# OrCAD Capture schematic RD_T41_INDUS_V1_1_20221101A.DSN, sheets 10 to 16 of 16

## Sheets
10 PAGE04_POWER-SUPPLY: size A3; note: POWER-SUPPLY
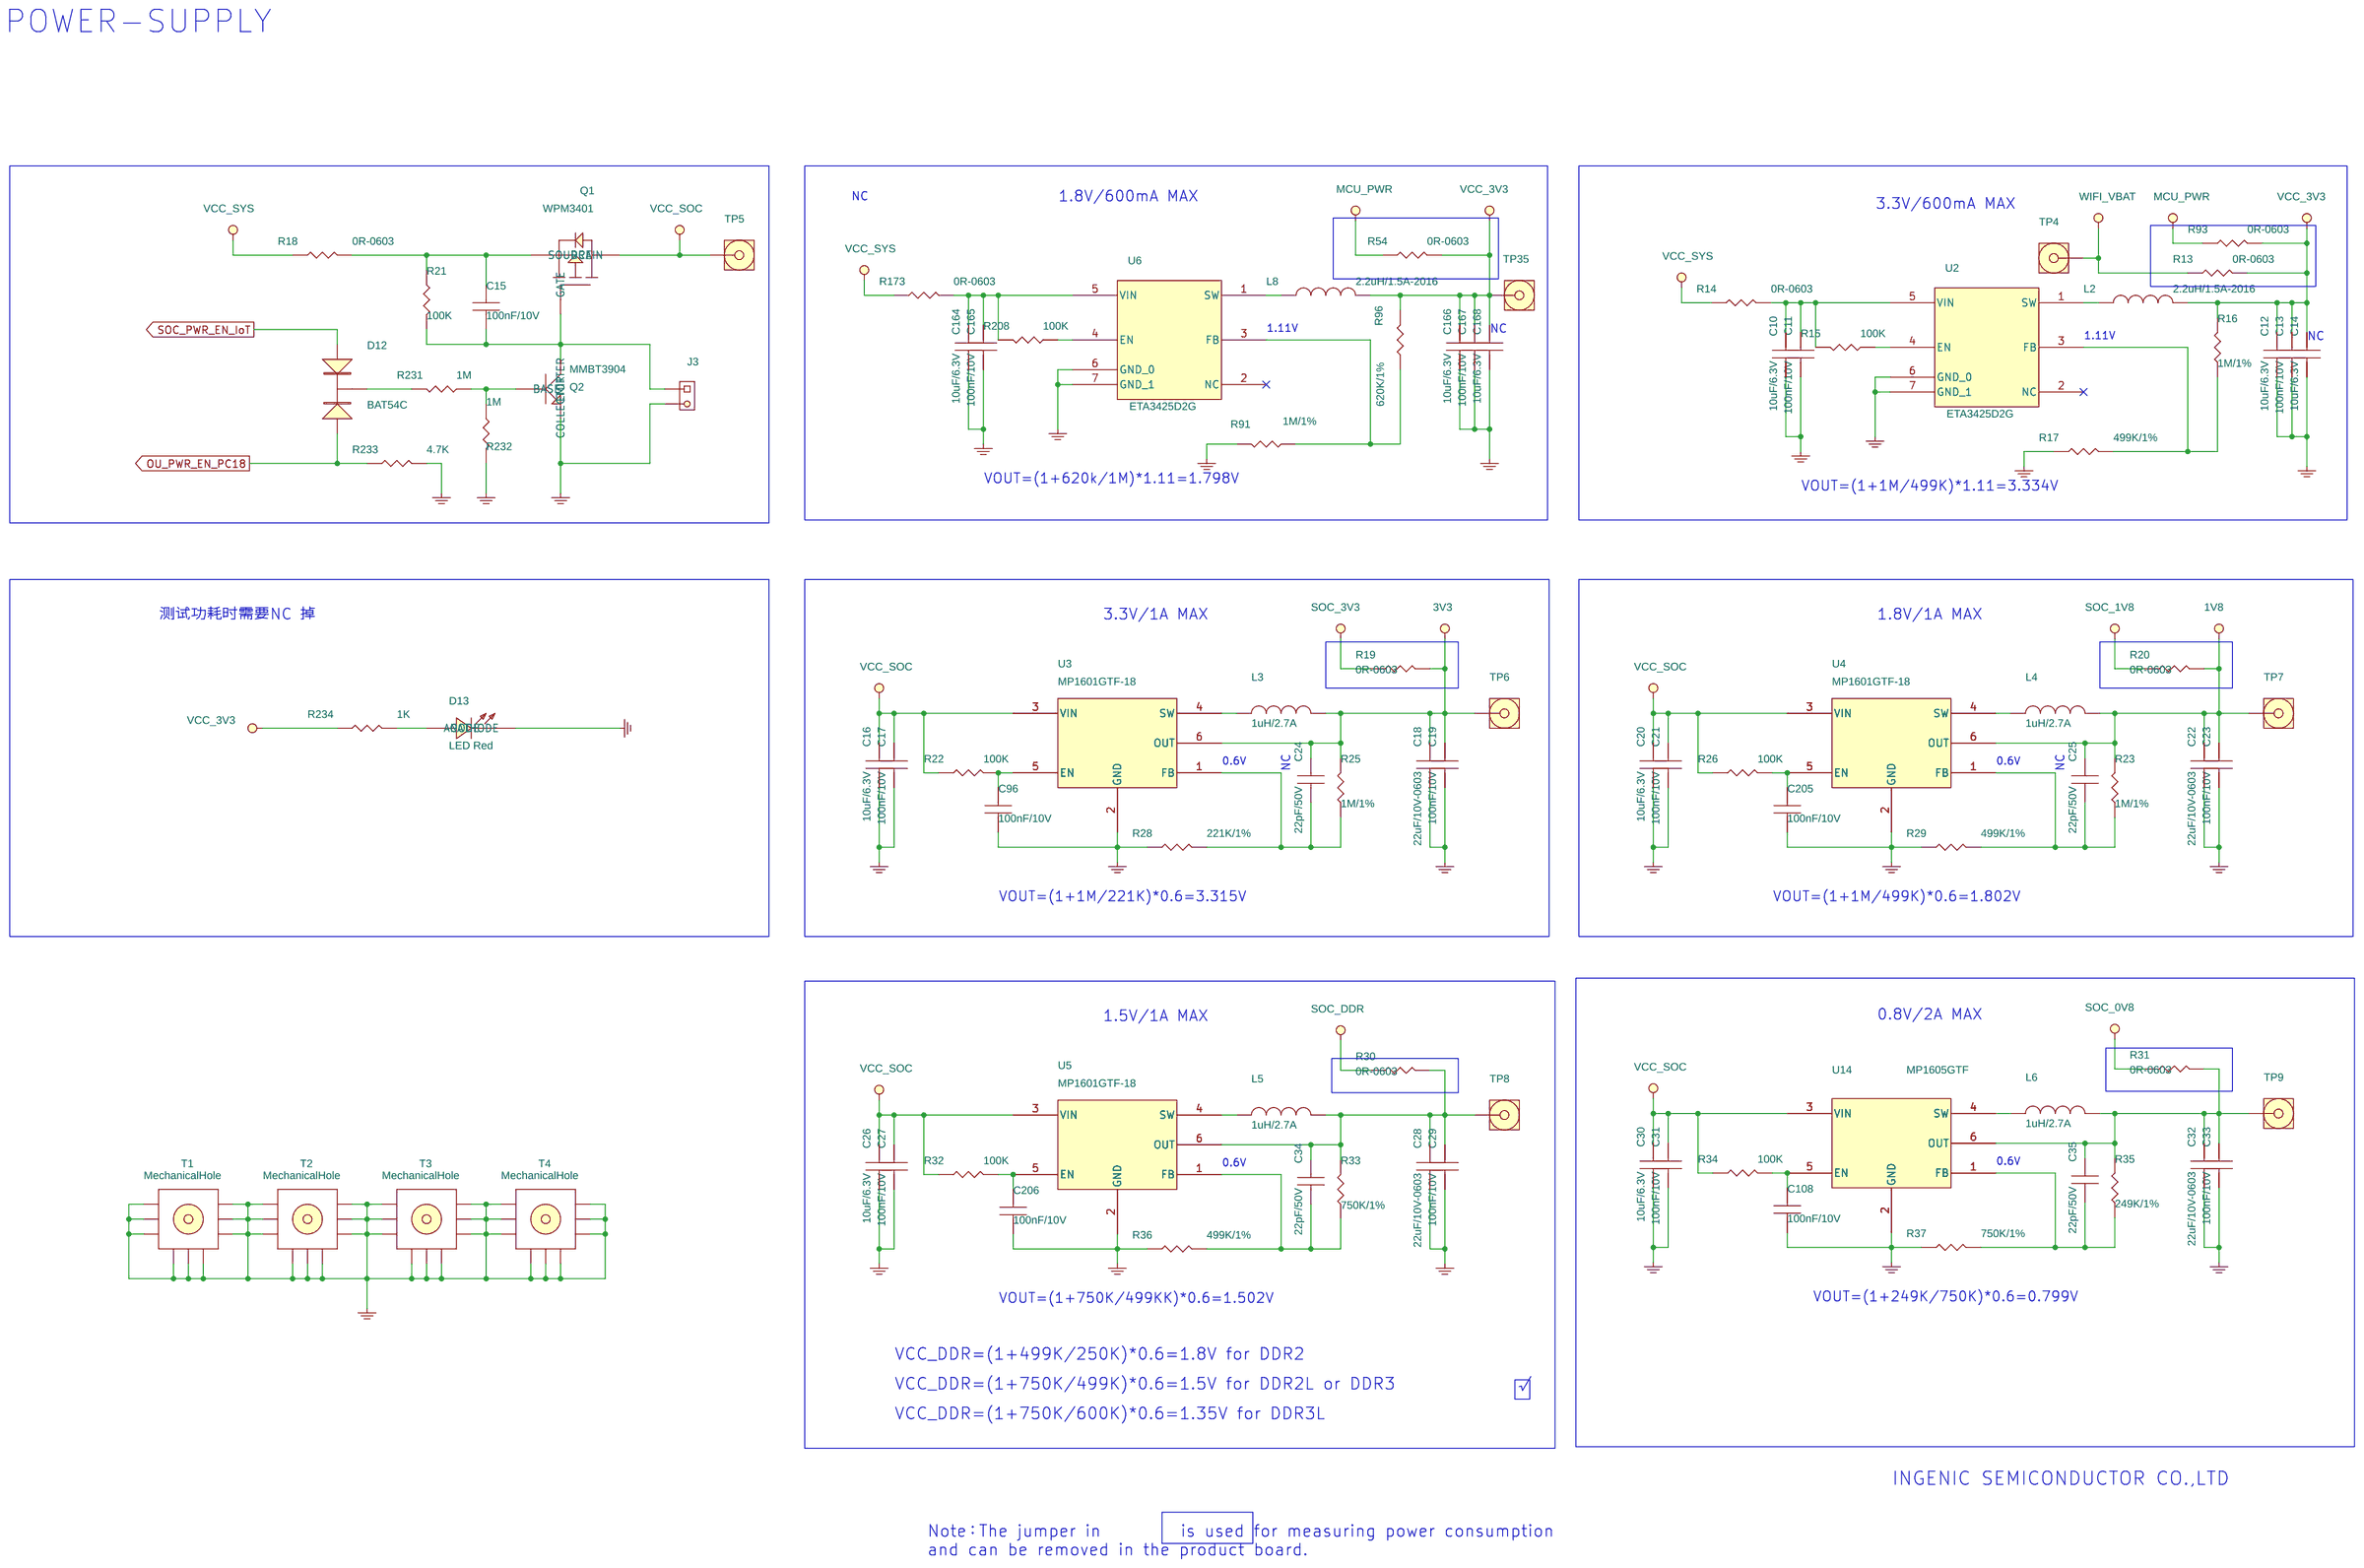
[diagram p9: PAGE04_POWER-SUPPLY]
11 PAGE05_T41_POWER: size A3; note: T41_POWER
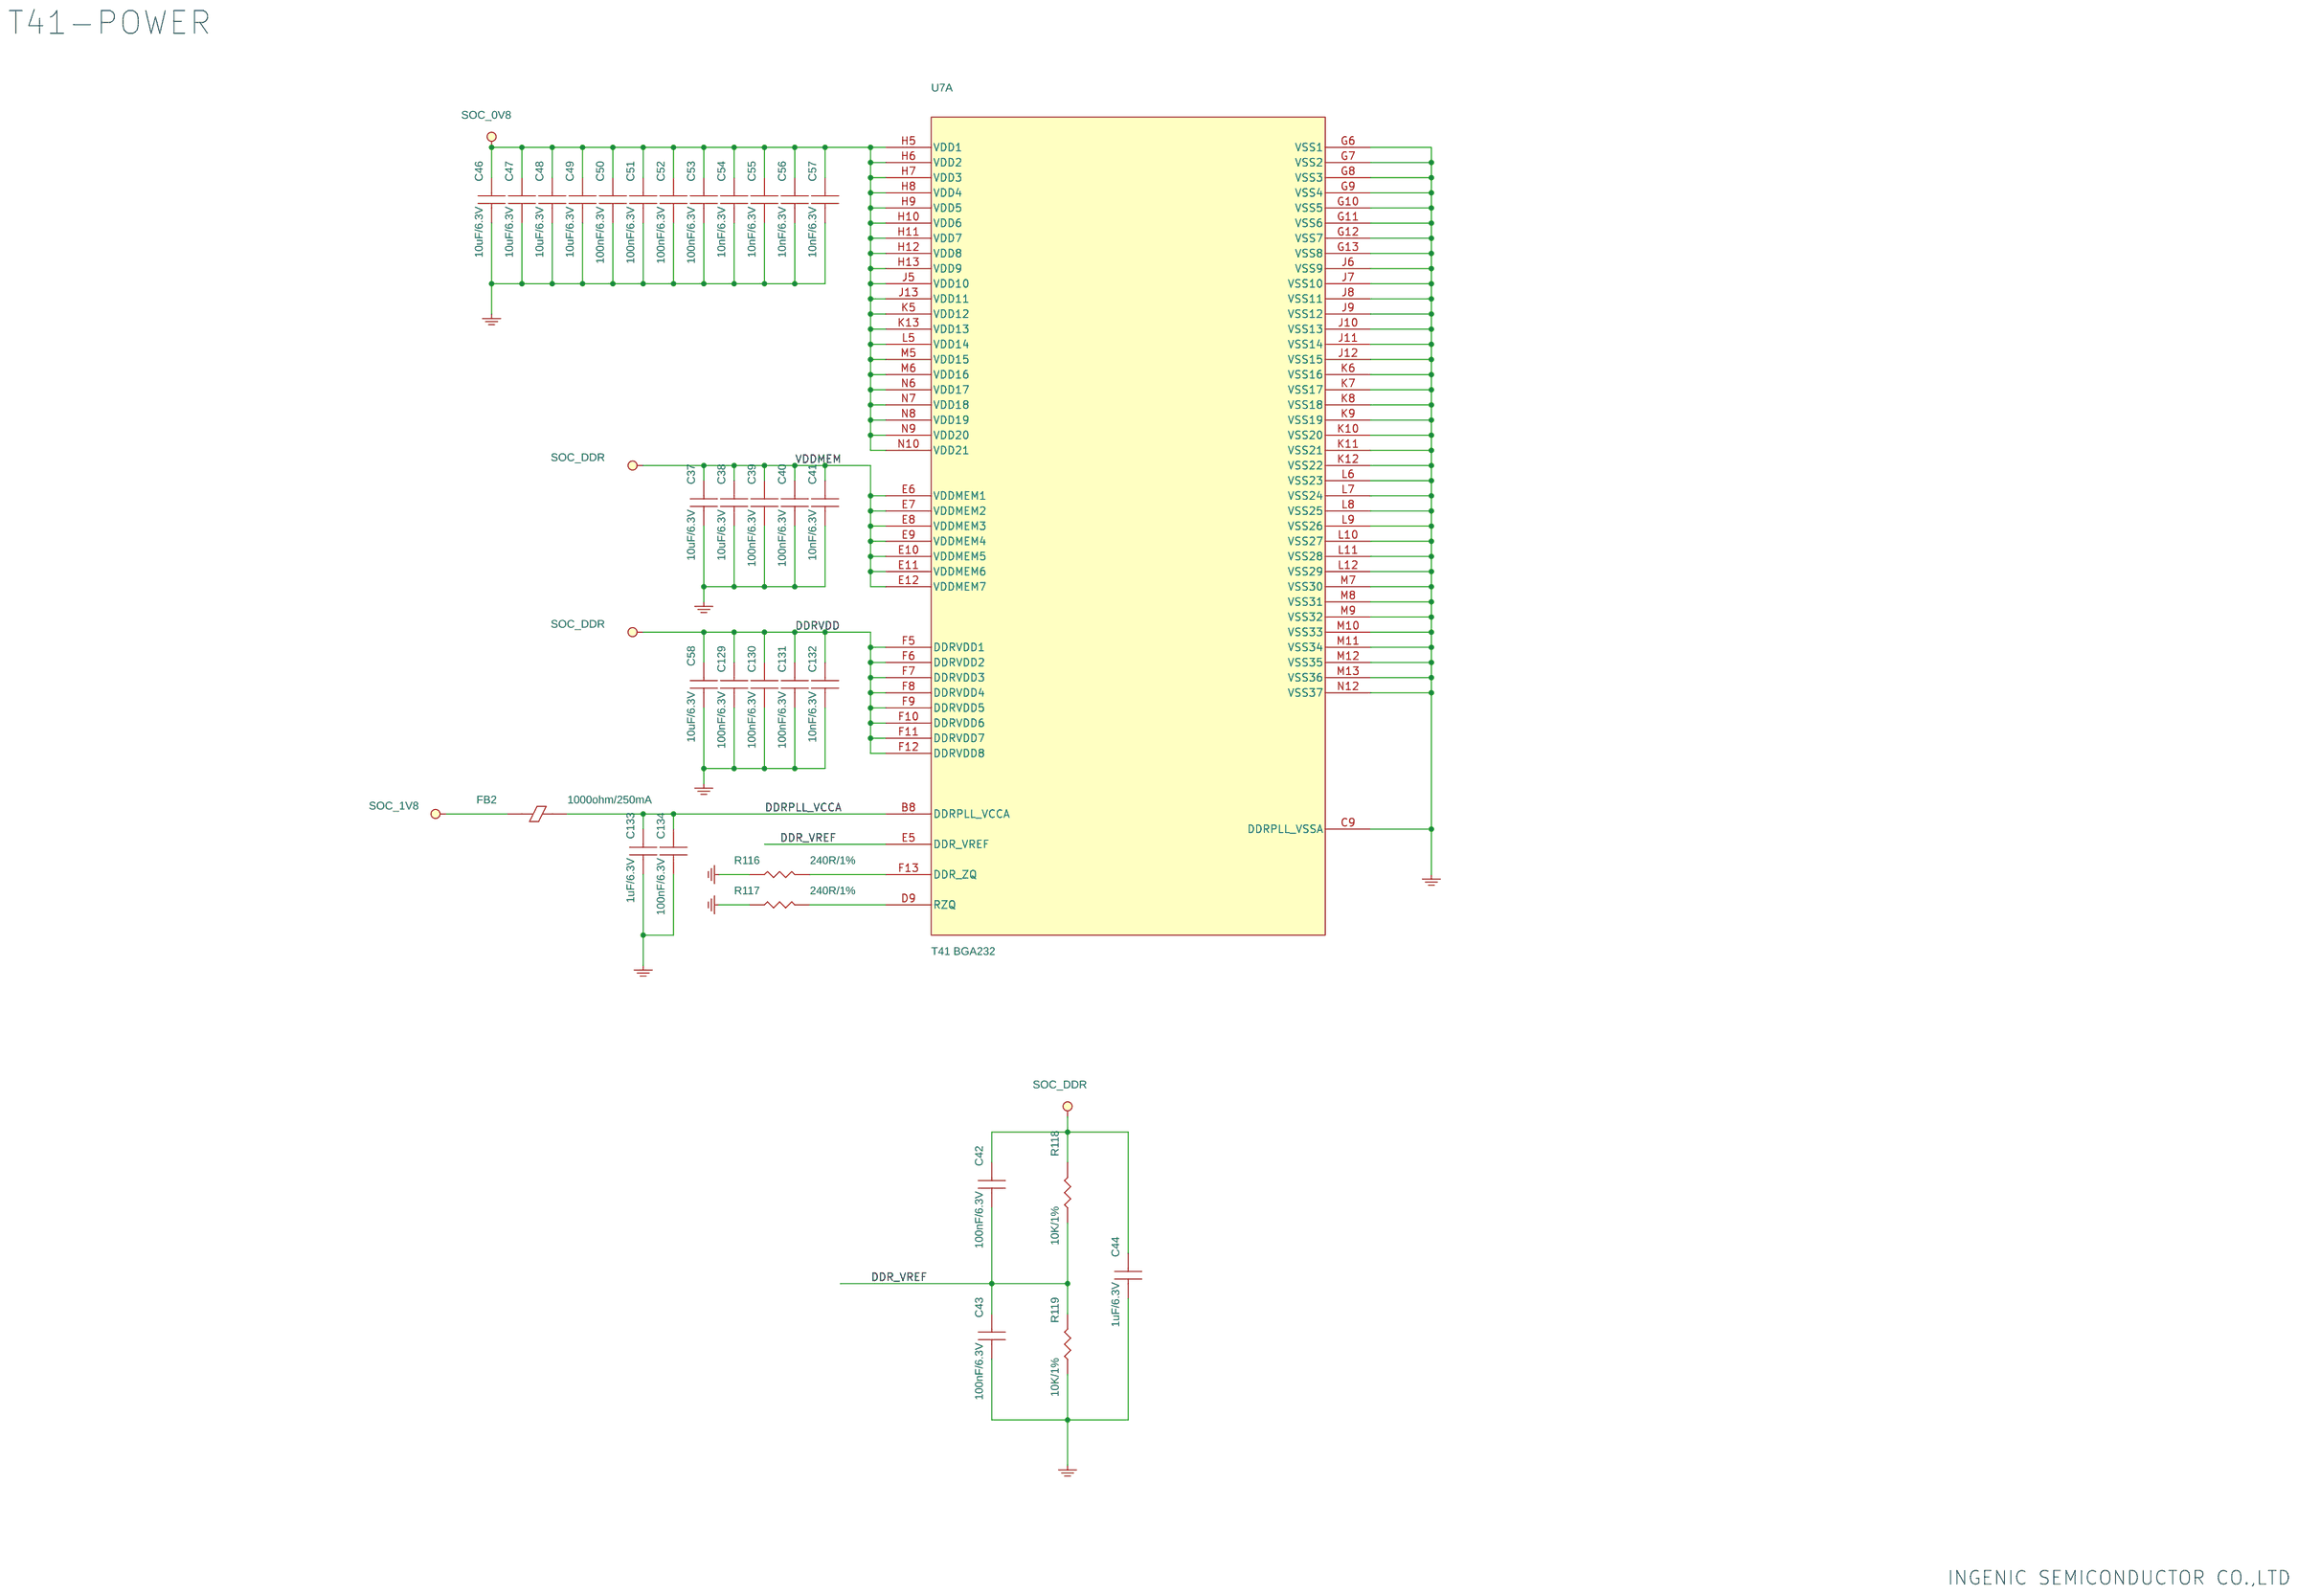
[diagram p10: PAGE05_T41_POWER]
12 PAGE06_T41_SYS_APeripheral: size A3; note: T41_SYS_APeripheral
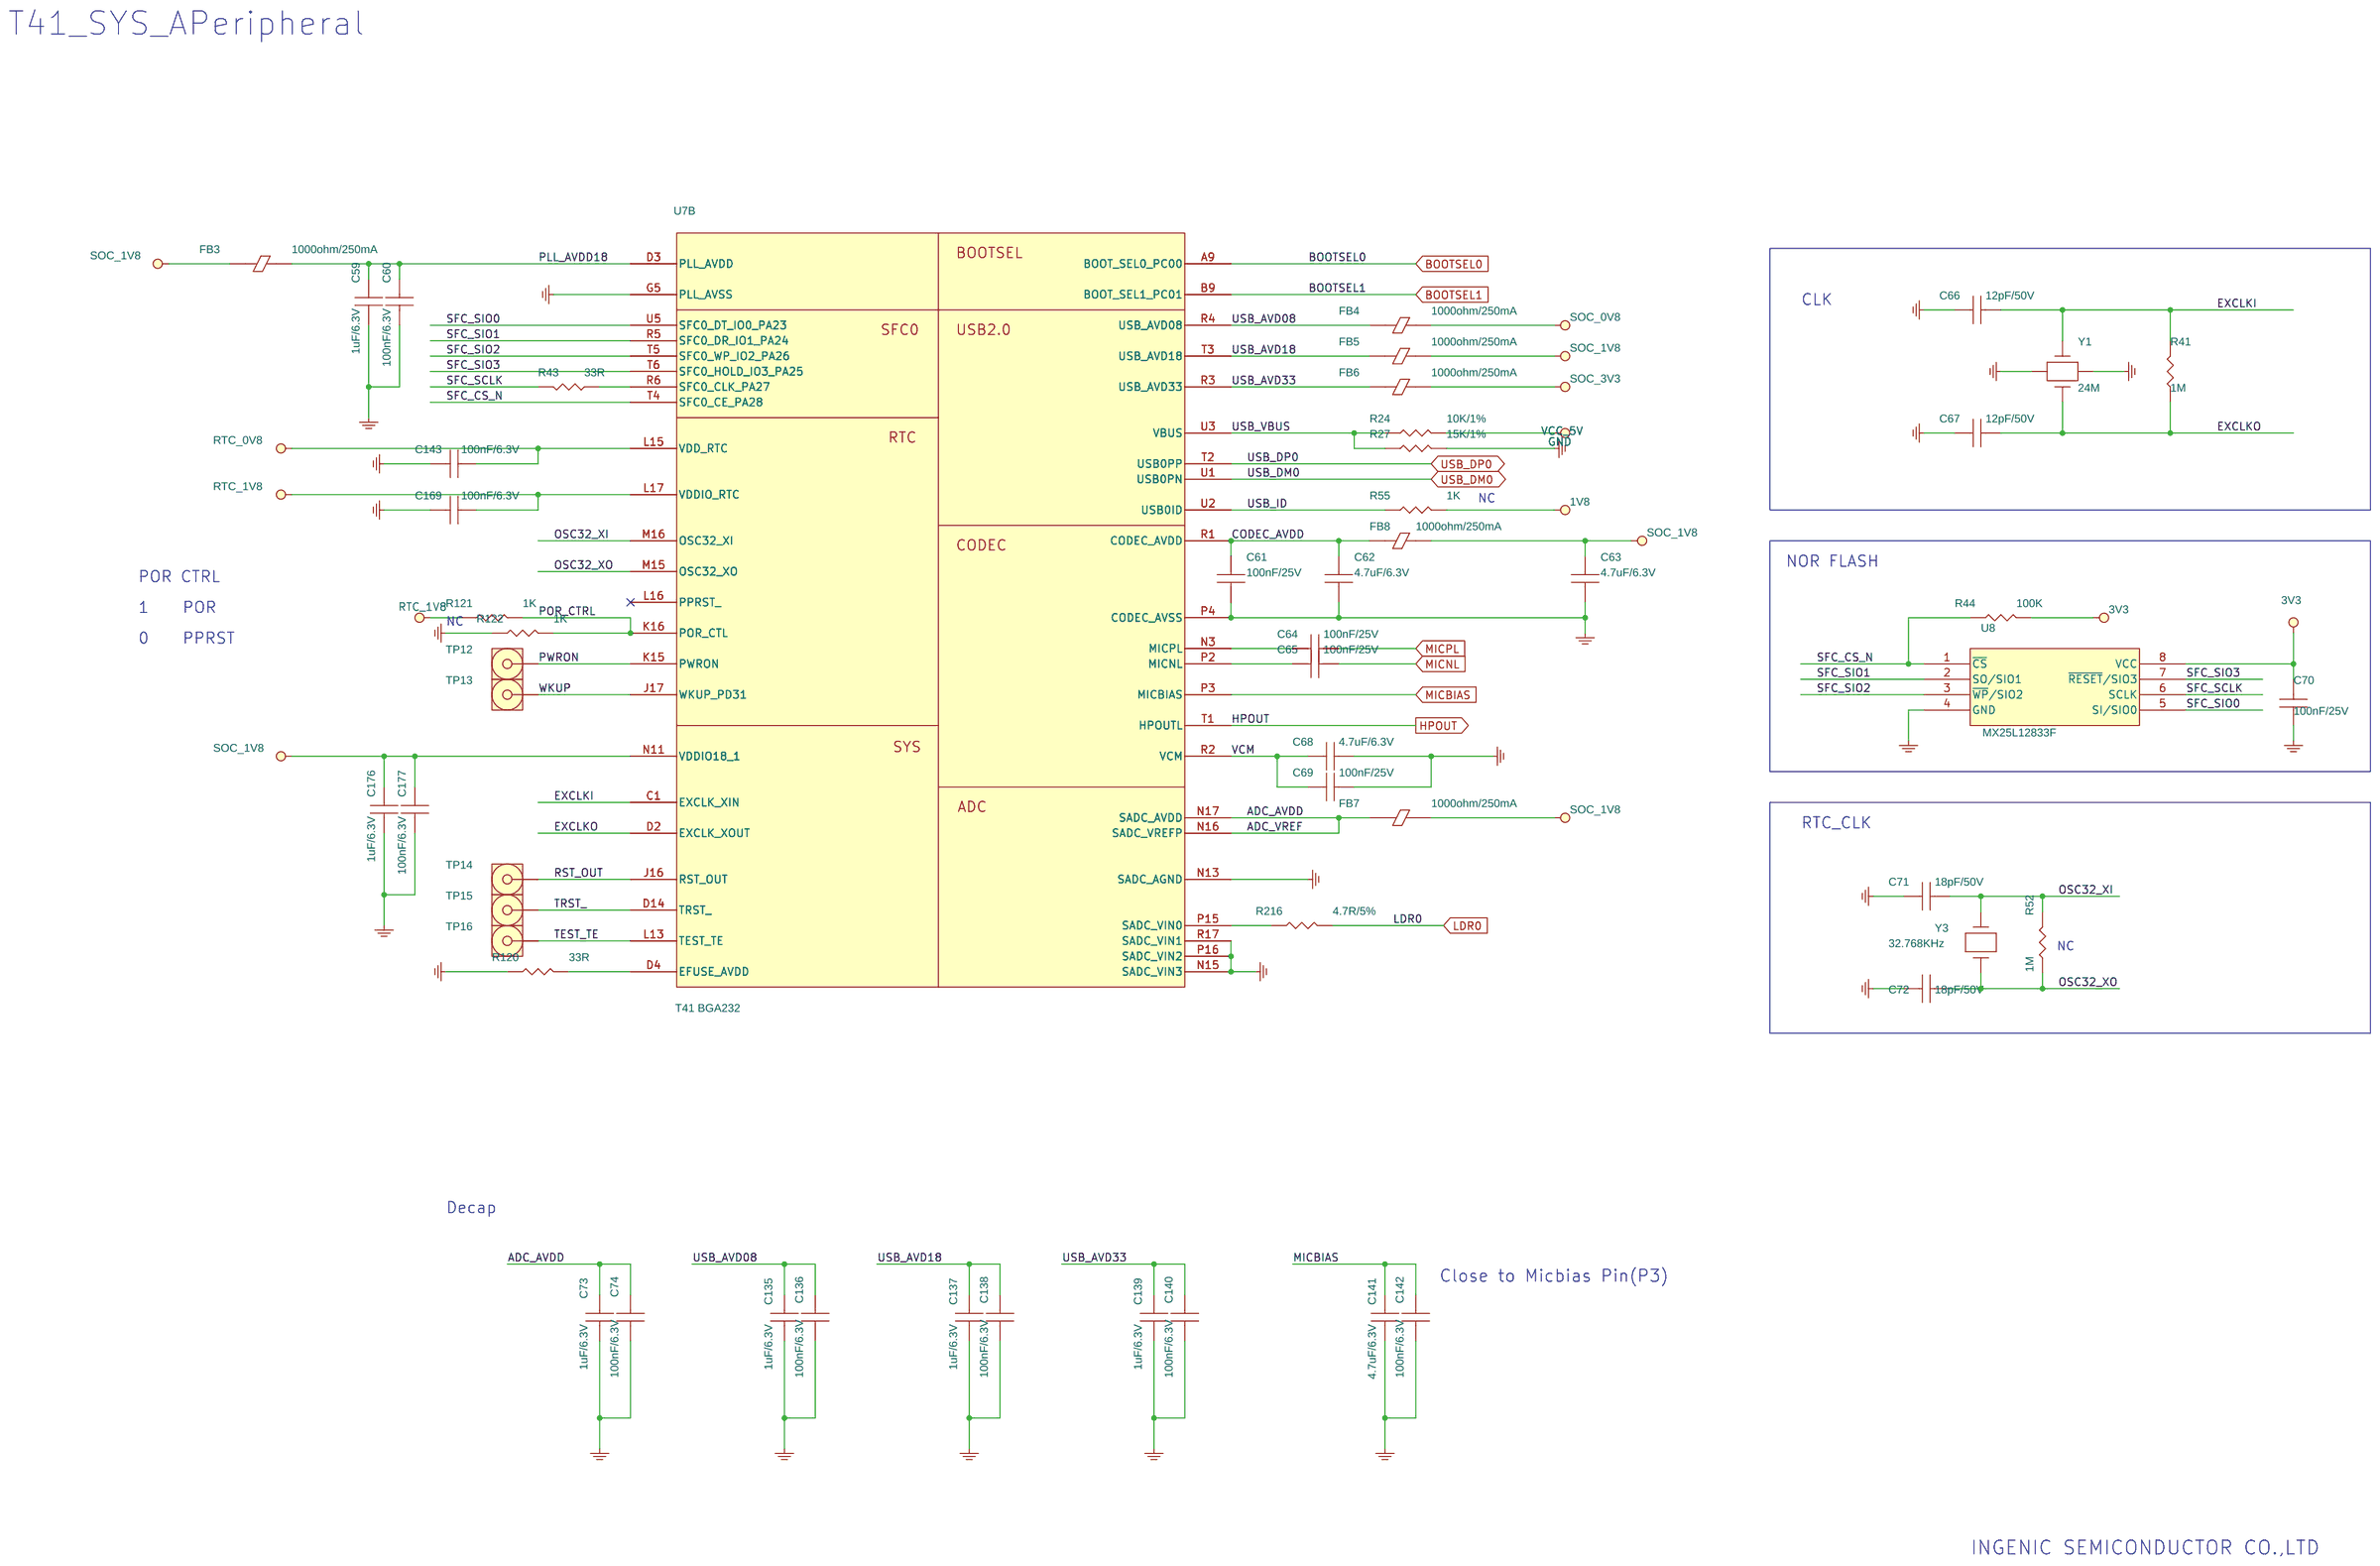
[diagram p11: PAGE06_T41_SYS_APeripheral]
13 PAGE09_SD_AUDIO_EMMC: size A3; note: SD_AUDIO_EMMC
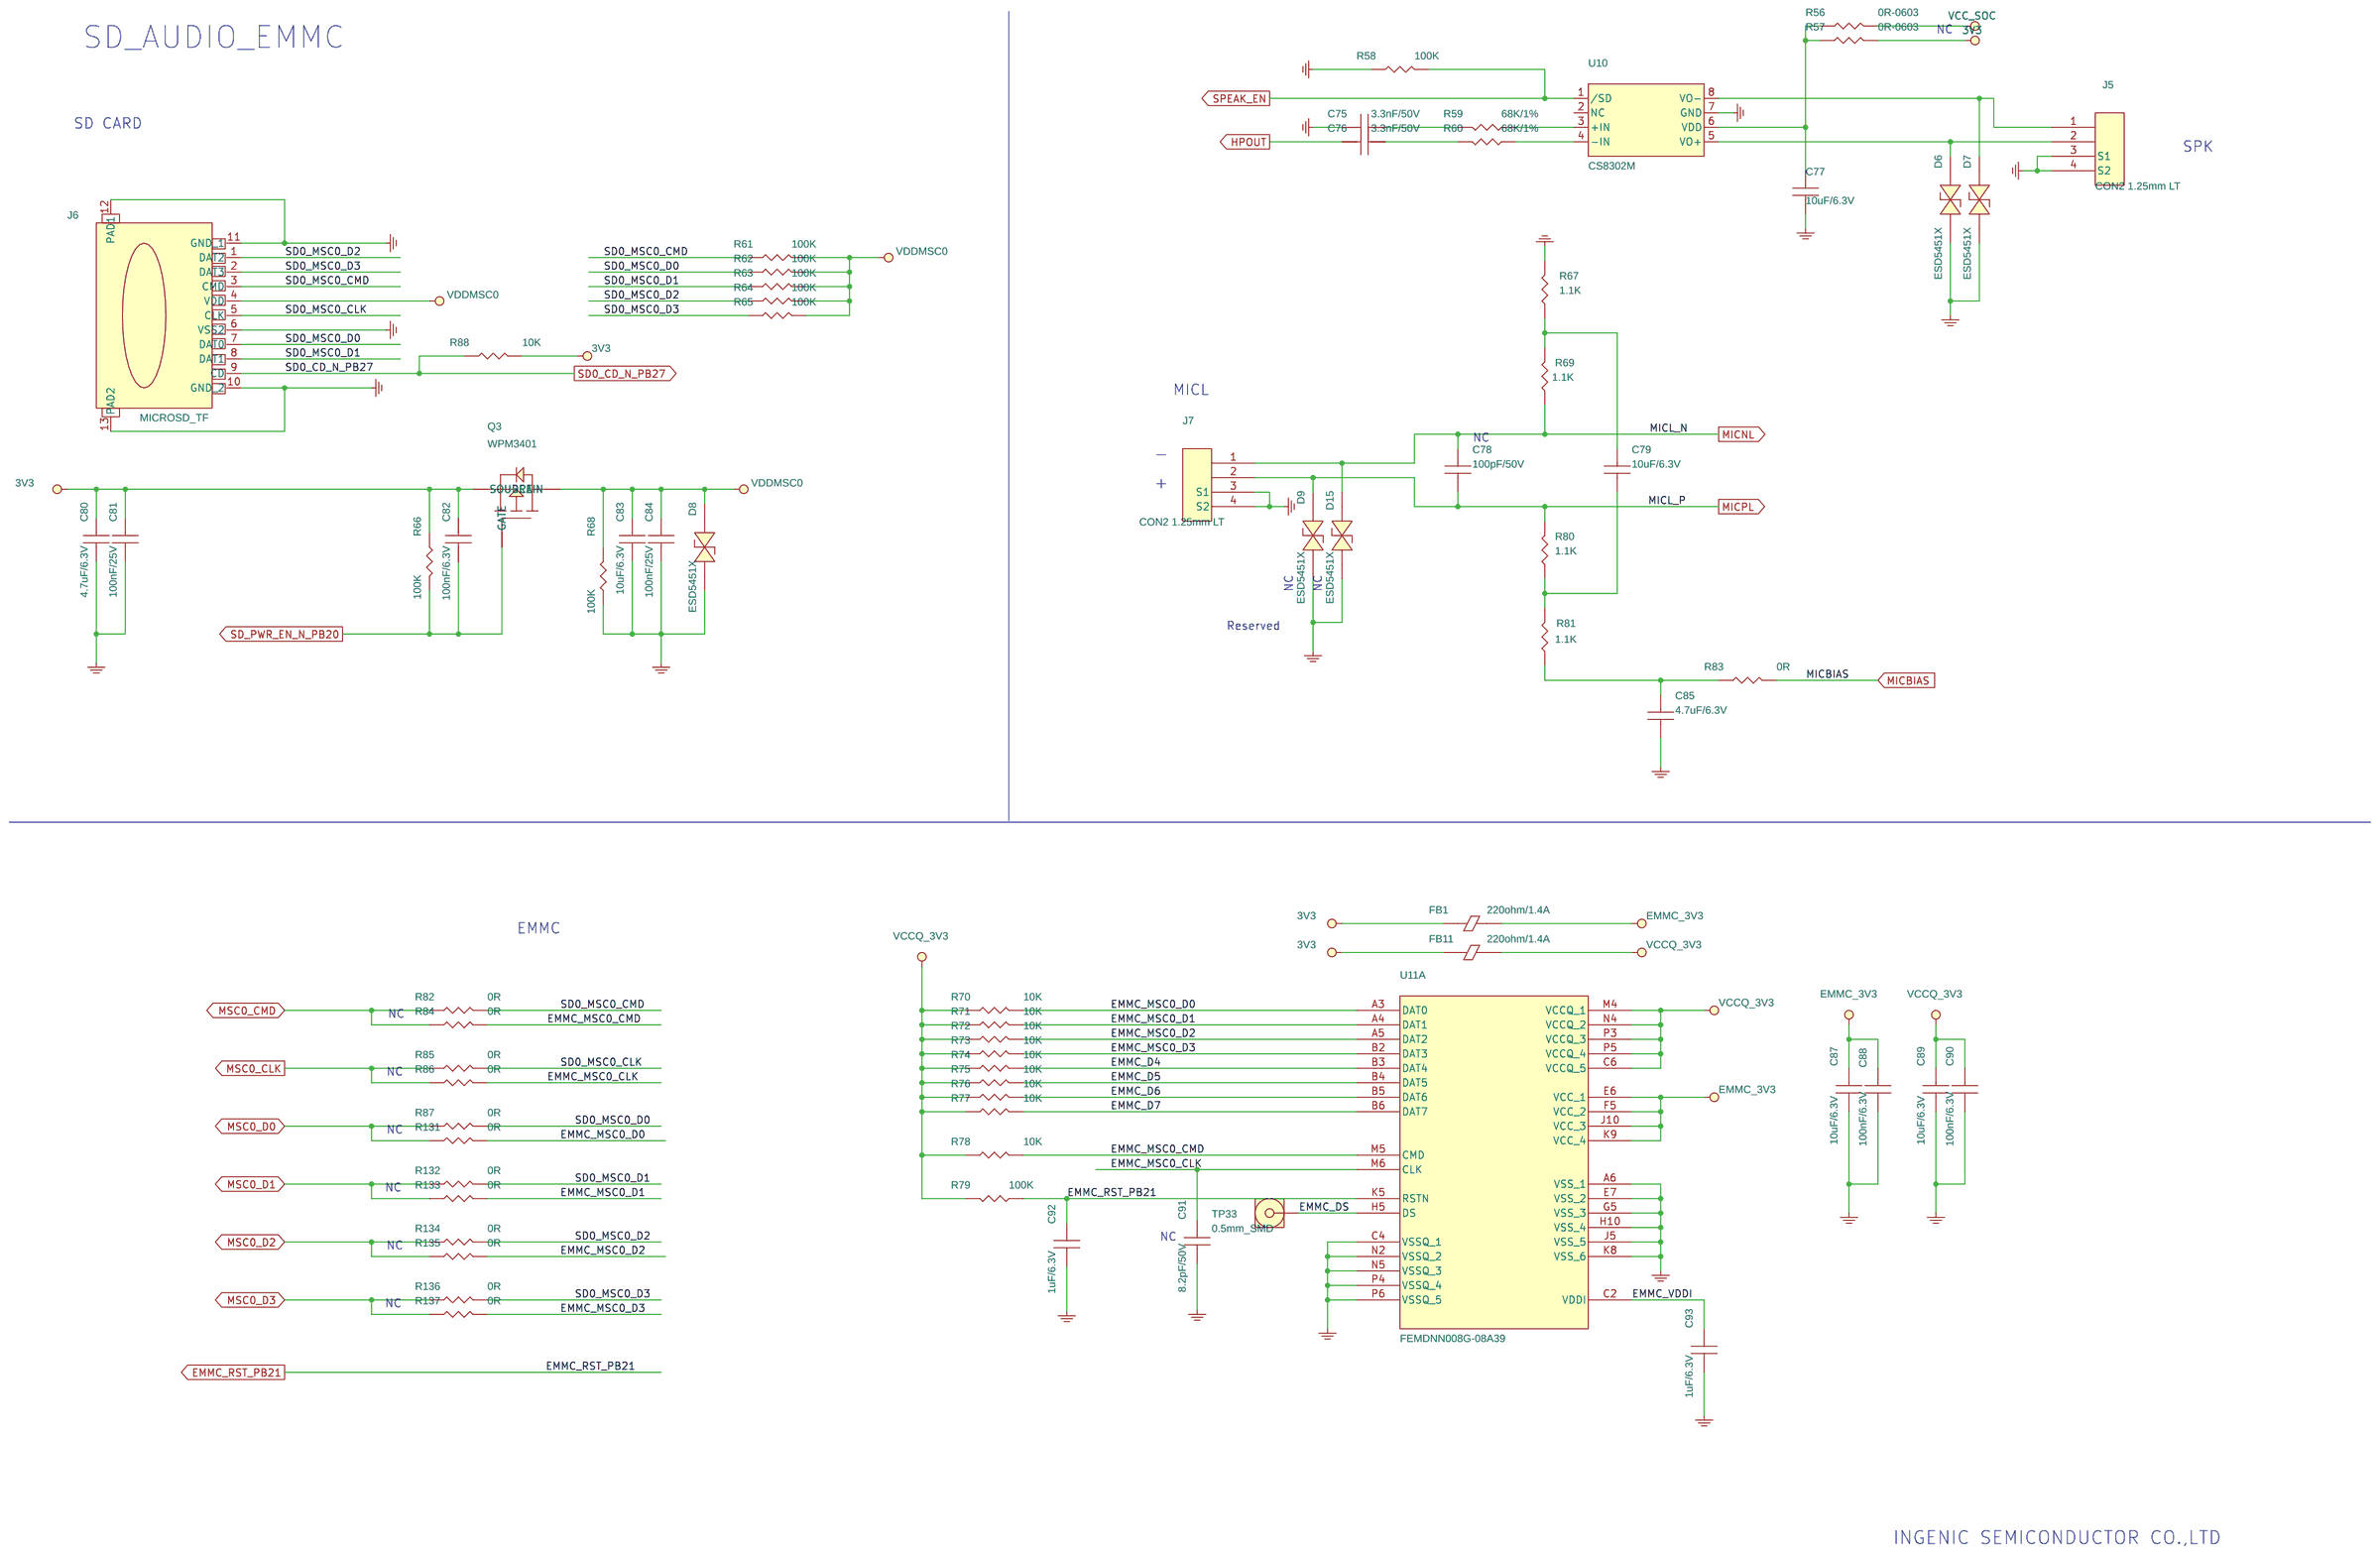
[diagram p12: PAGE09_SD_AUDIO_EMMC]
14 PAGE15_KEY_LED_RTC_BOOT: size A3; note: KEY_LED_RTC_BOOT
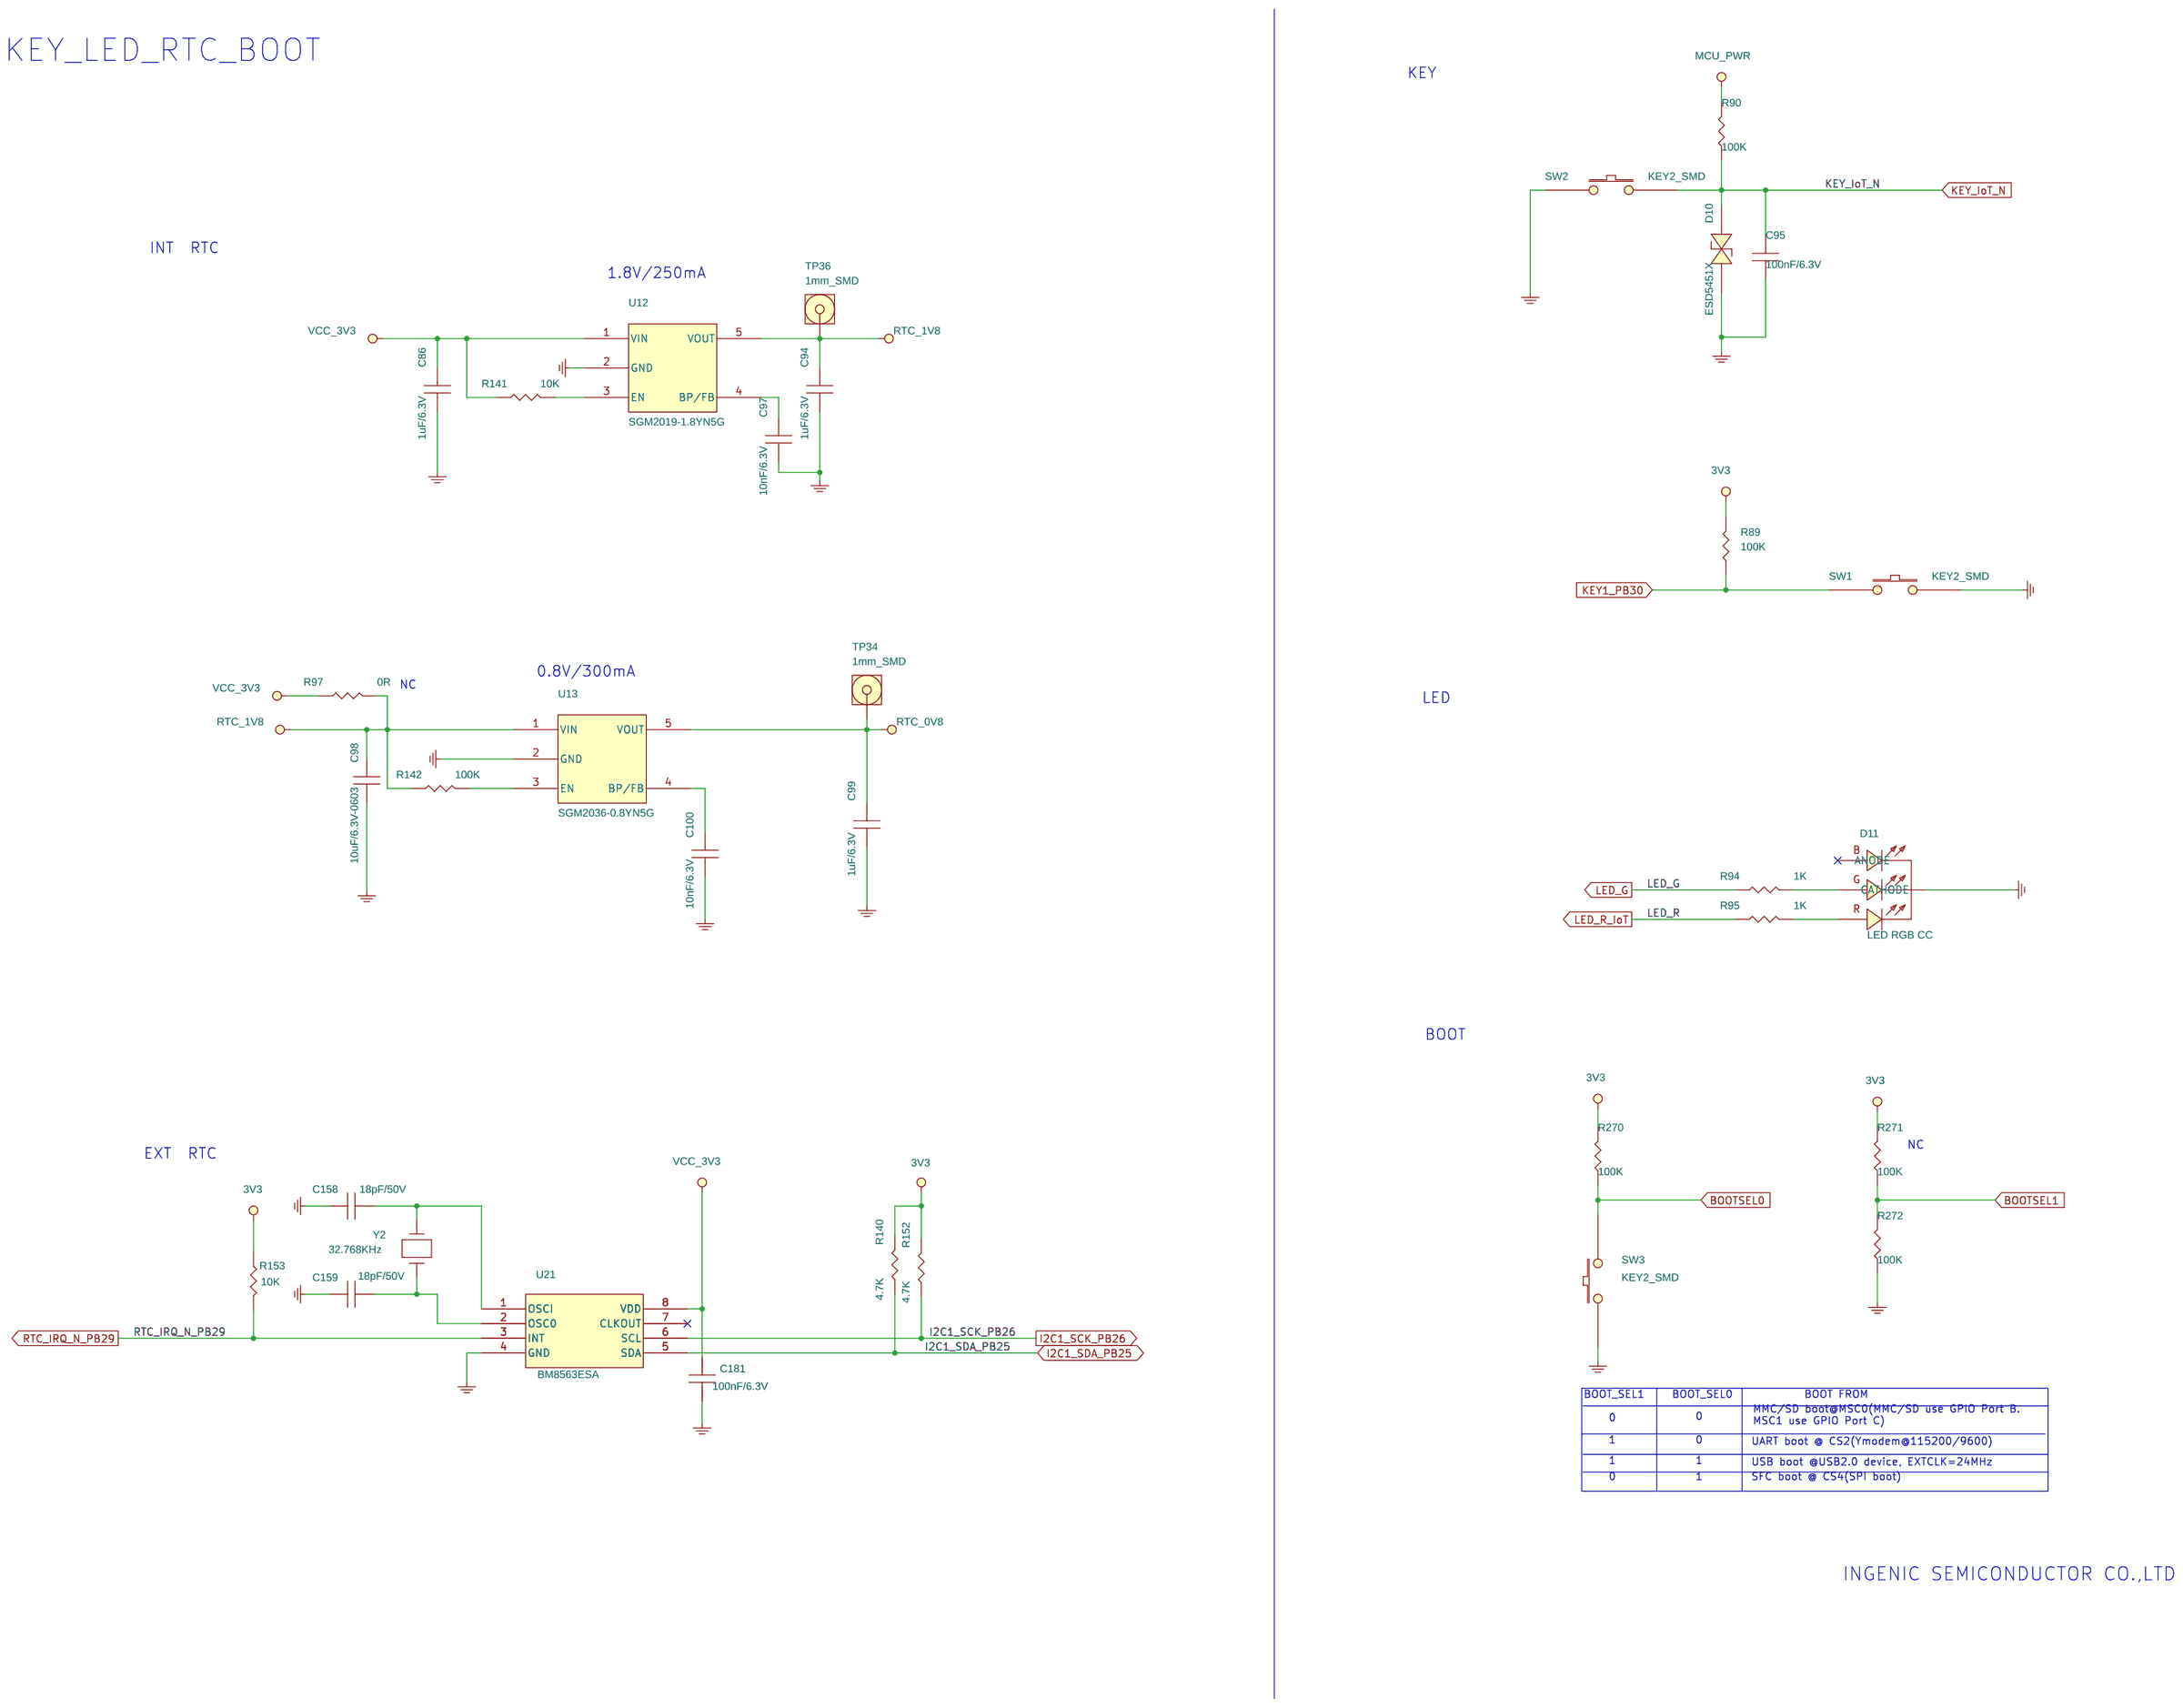
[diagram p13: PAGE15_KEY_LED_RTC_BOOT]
15 PAGE11_MIPI_DVP_CAMERA: size A3; note: MIPI_DVP_CAMERA
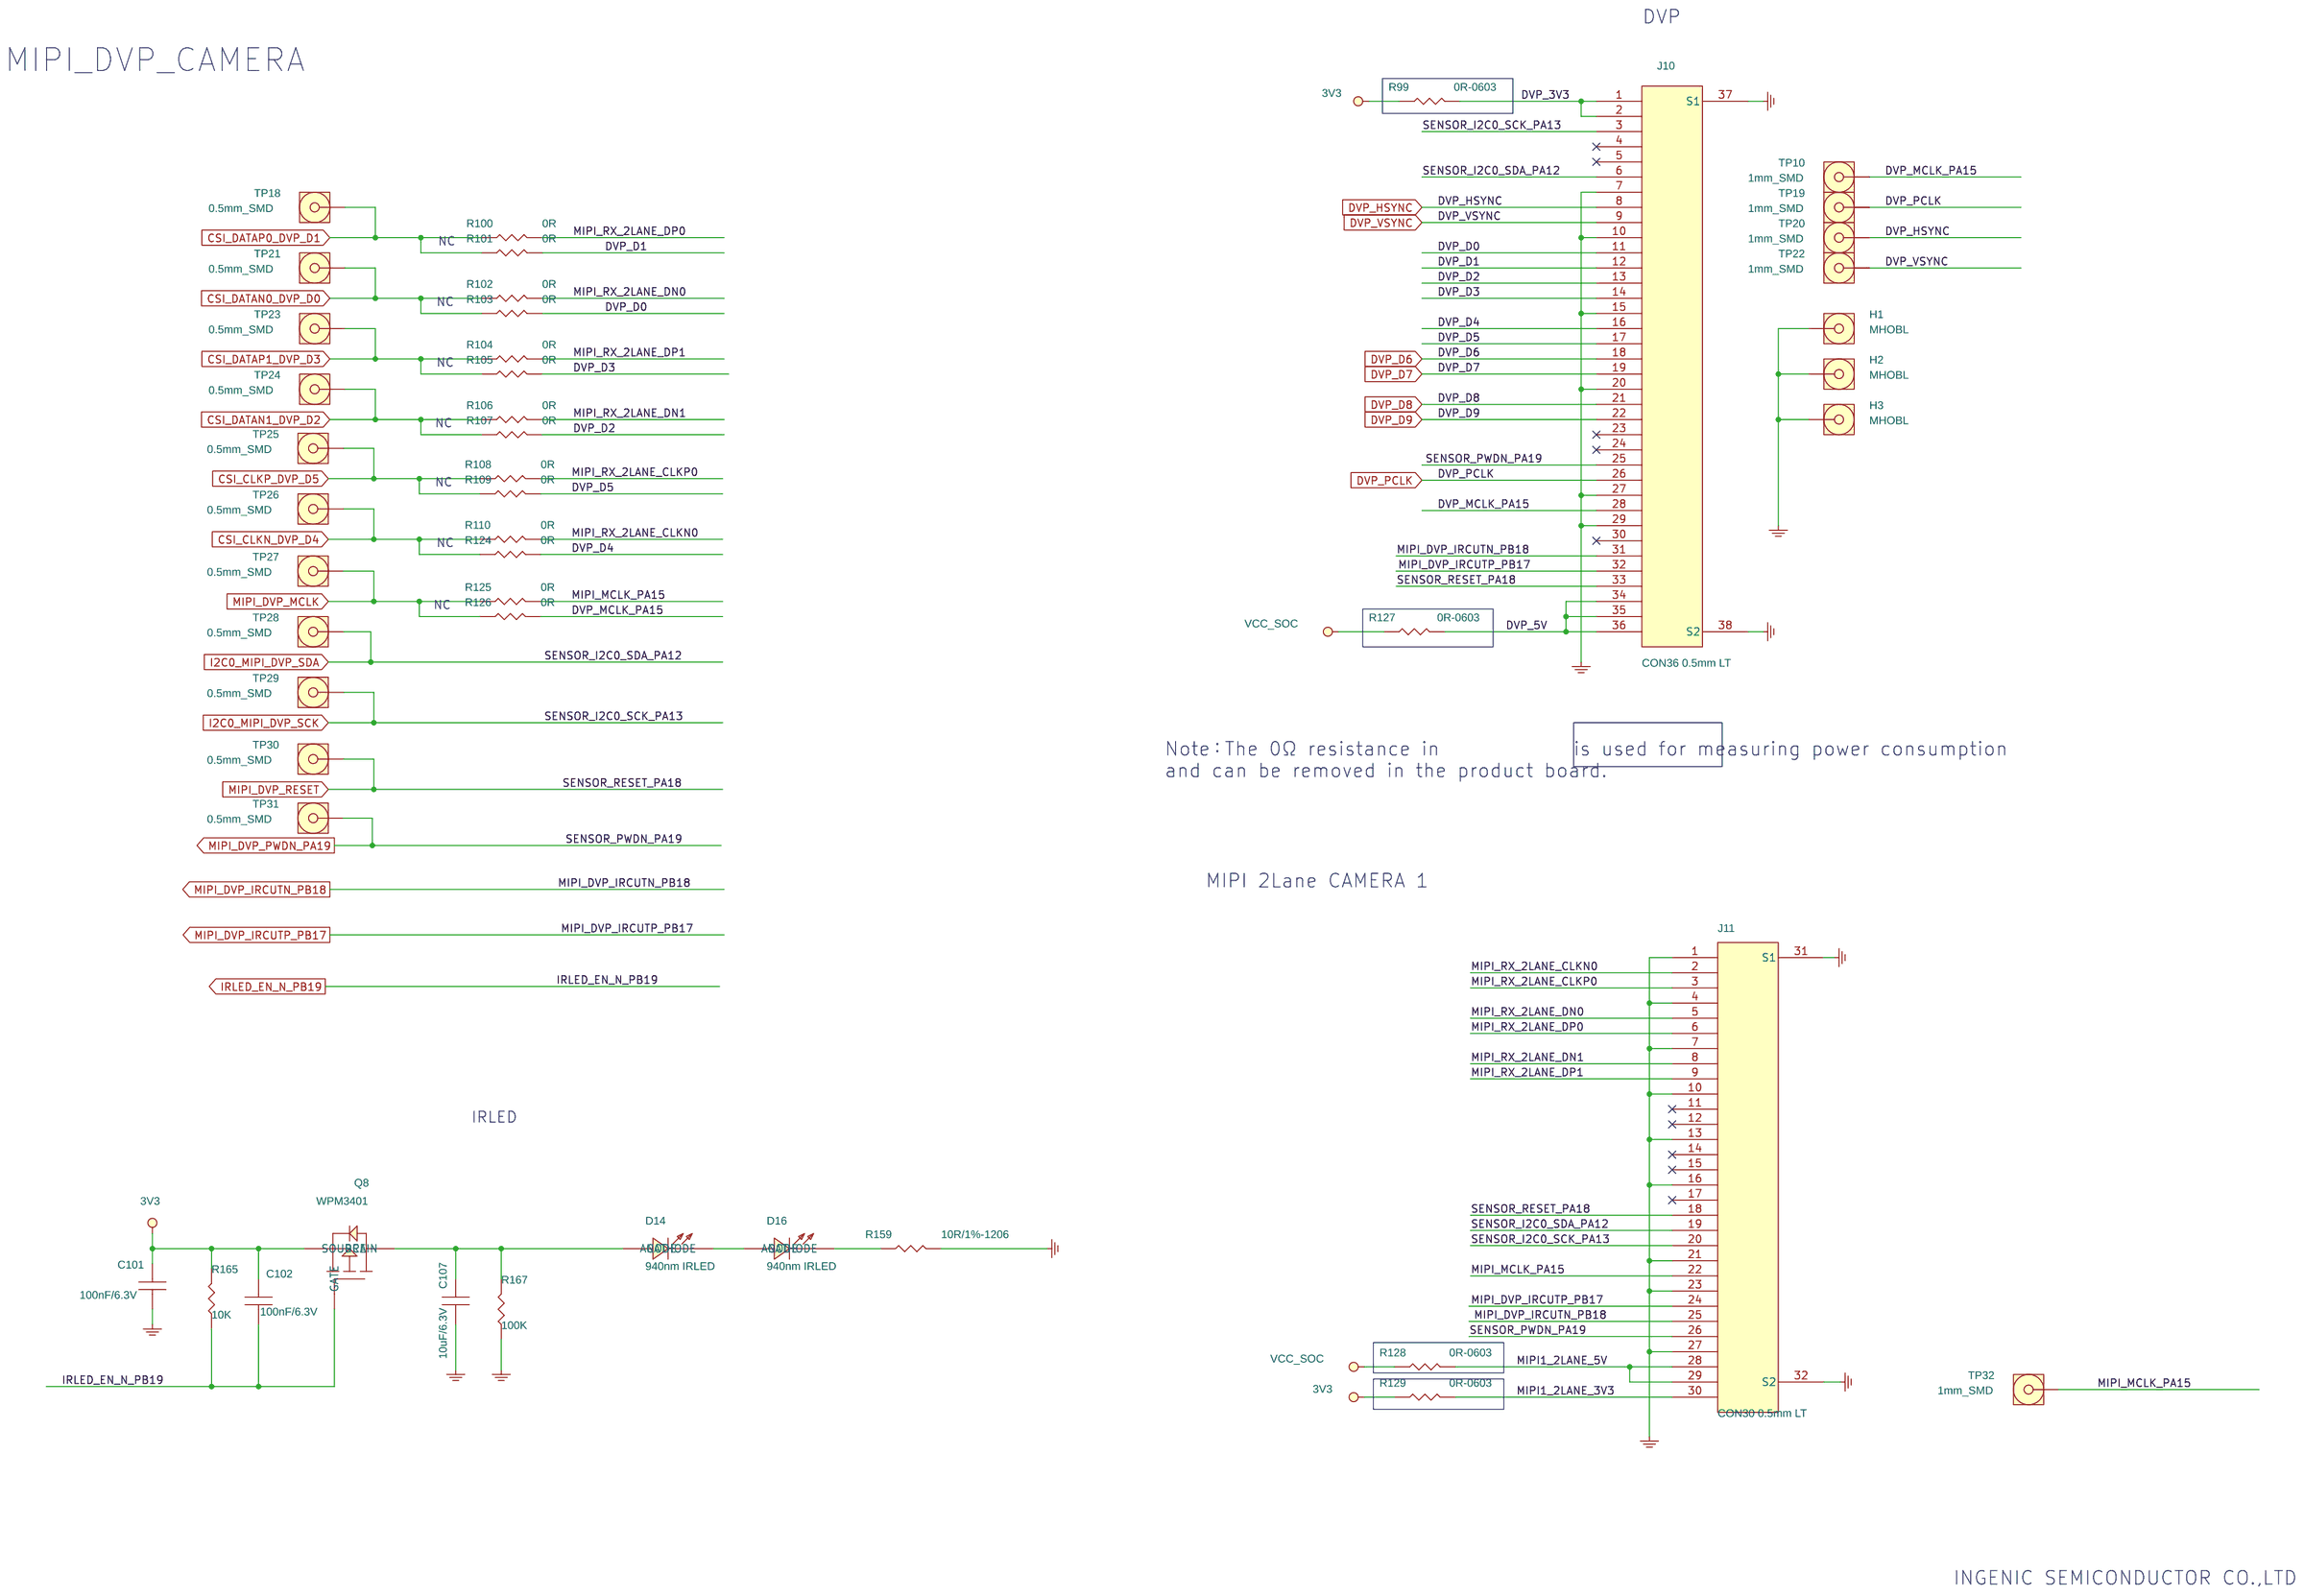
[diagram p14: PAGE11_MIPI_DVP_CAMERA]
16 PAGE16_REVISION-HISTORY: note: REVISION-HISTORY
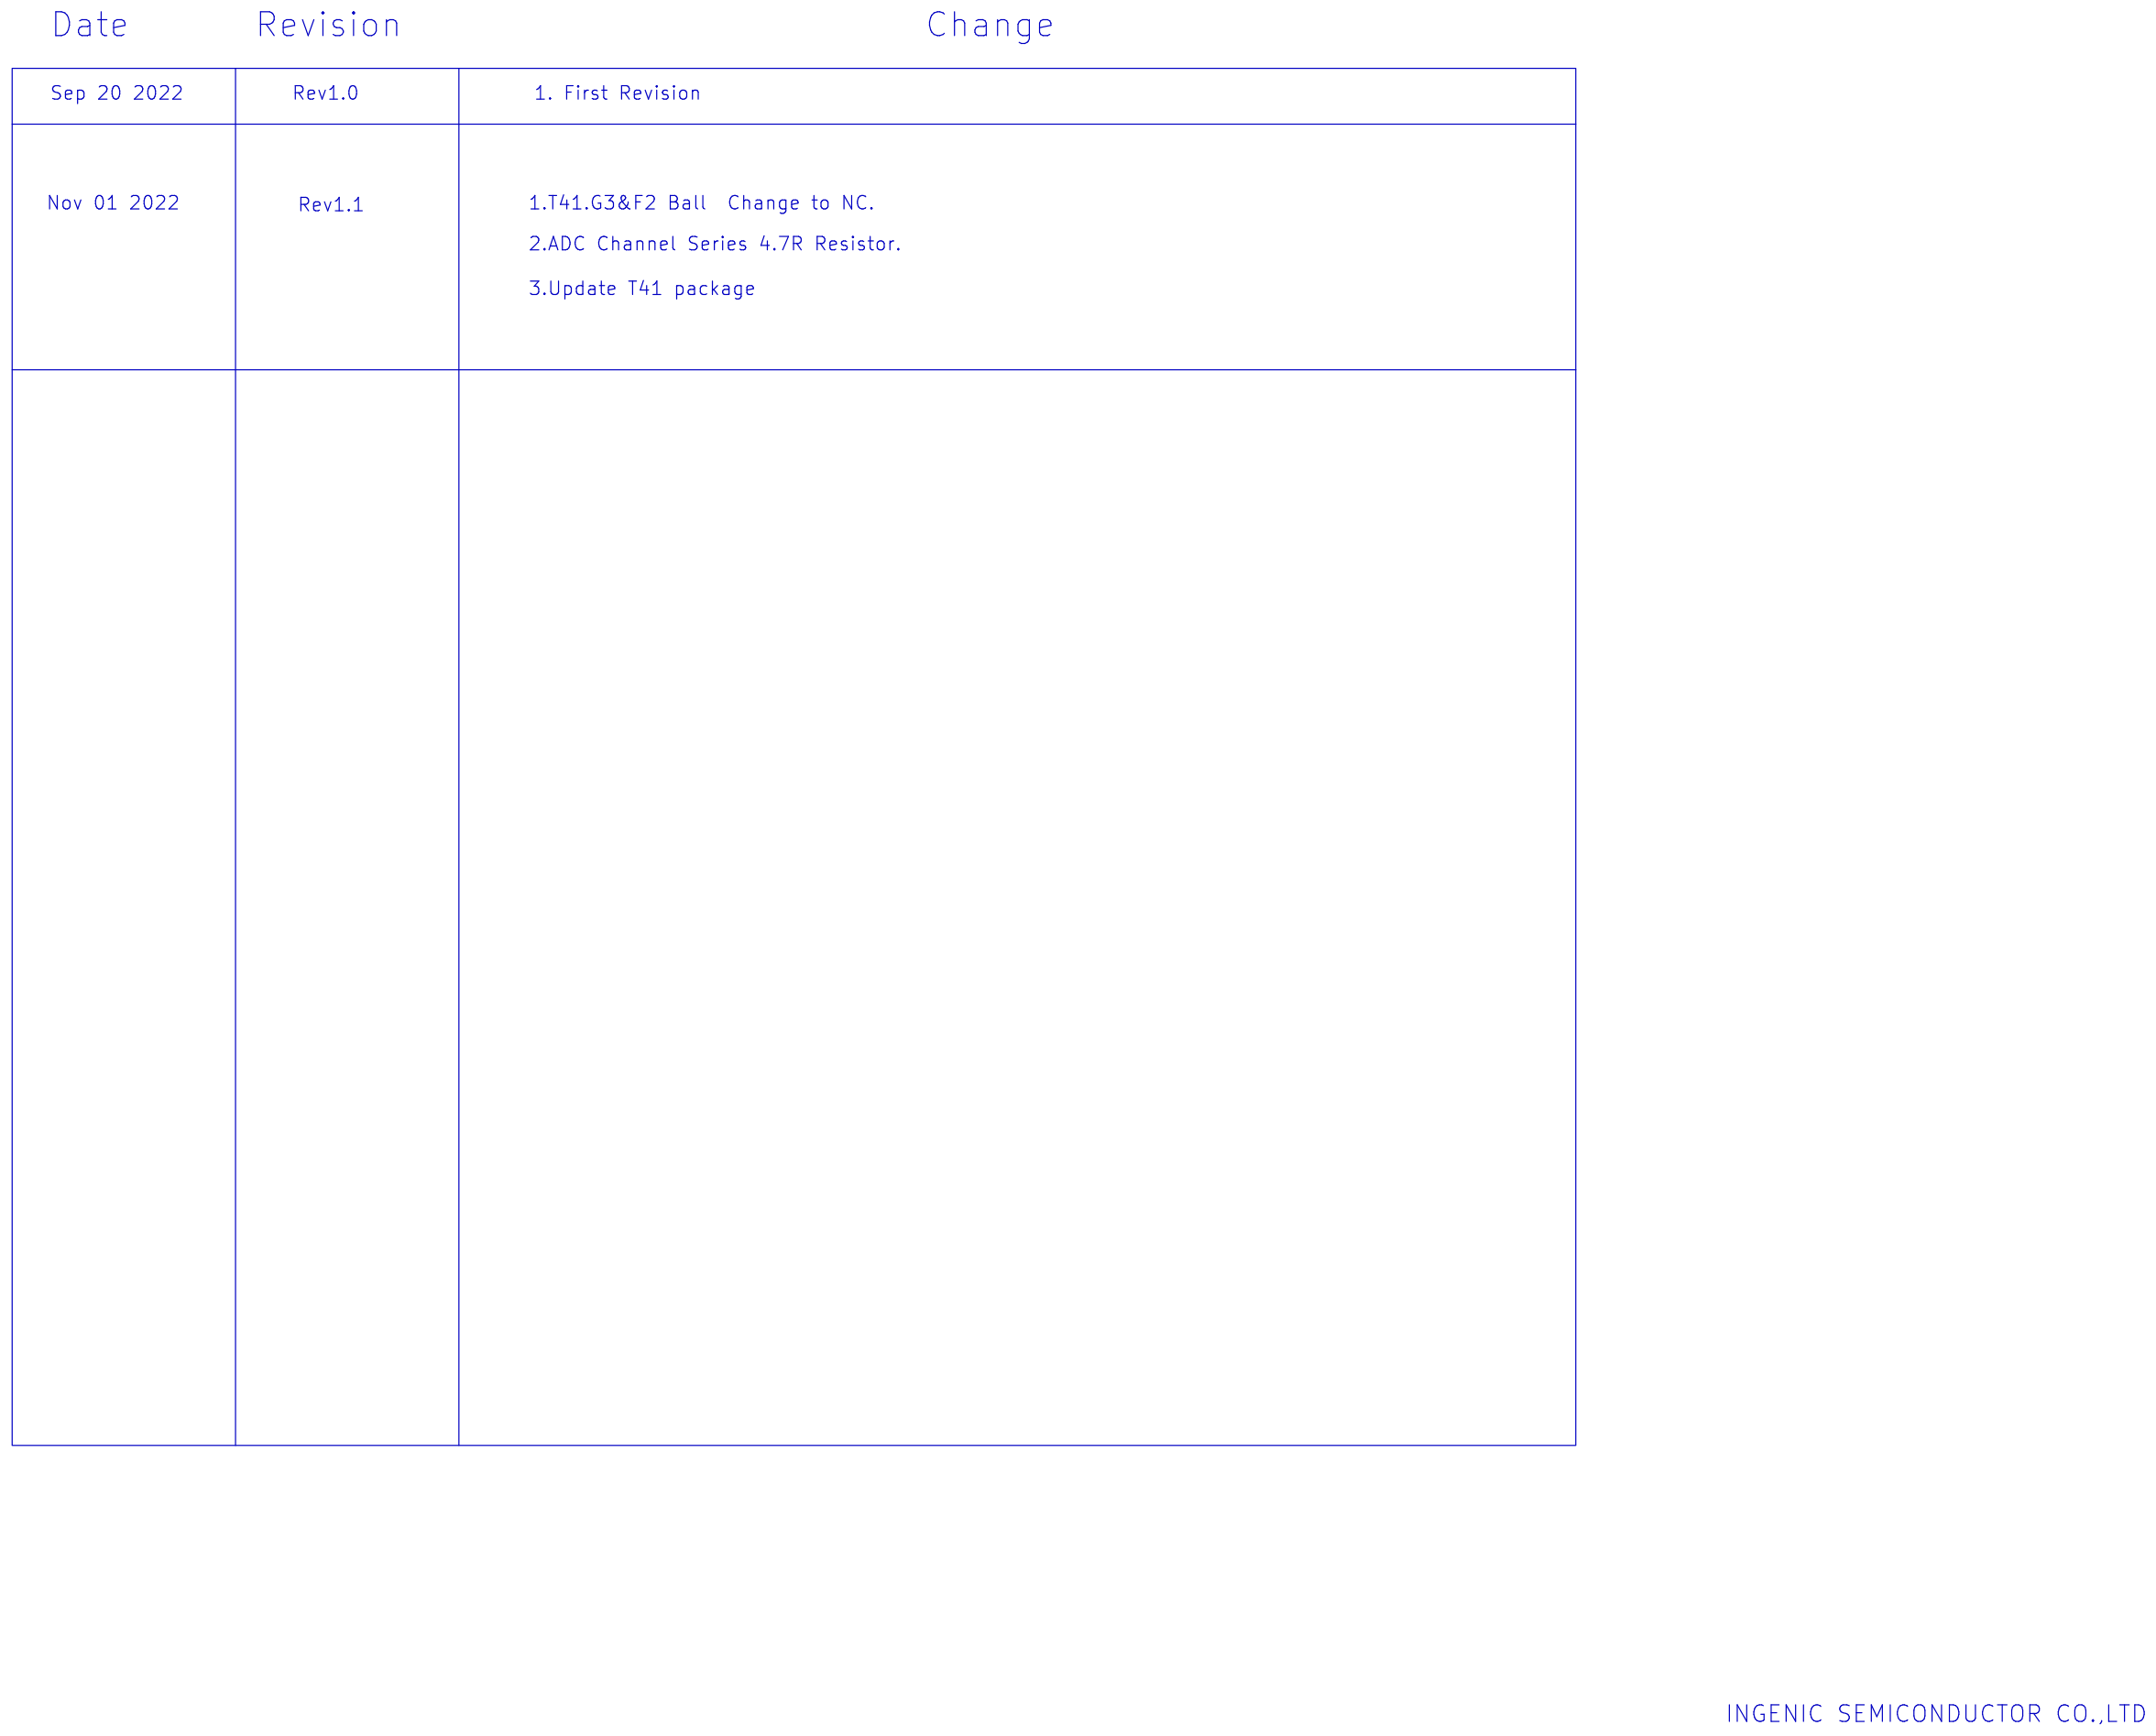
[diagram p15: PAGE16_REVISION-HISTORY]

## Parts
sheet PAGE04_POWER-SUPPLY
C10  10uF/6.3V  [C0402_E]
C11  100nF/10V  [C0402]
C12  10uF/6.3V  [C0402_E]
C13  100nF/10V  [C0402]
C14  10uF/6.3V  [C0402_E]
C15  100nF/10V  [C0402]
C16  10uF/6.3V  [C0402_E]
C17  100nF/10V  [C0402]
C18  22uF/10V-0603  [C0603]
C19  100nF/10V  [C0402]
C20  10uF/6.3V  [C0402_E]
C21  100nF/10V  [C0402]
C22  22uF/10V-0603  [C0603]
C23  100nF/10V  [C0402]
C24  22pF/50V  [C0402]
C25  22pF/50V  [C0402]
C26  10uF/6.3V  [C0402_E]
C27  100nF/10V  [C0402]
C28  22uF/10V-0603  [C0603]
C29  100nF/10V  [C0402]
C30  10uF/6.3V  [C0402_E]
C31  100nF/10V  [C0402]
C32  22uF/10V-0603  [C0603]
C33  100nF/10V  [C0402]
C34  22pF/50V  [C0402]
C35  22pF/50V  [C0402]
C96  100nF/10V  [C0402]
C108  100nF/10V  [C0402]
C164  10uF/6.3V  [C0402_E]
C165  100nF/10V  [C0402]
C166  10uF/6.3V  [C0402_E]
C167  100nF/10V  [C0402]
C168  10uF/6.3V  [C0402_E]
C205  100nF/10V  [C0402]
C206  100nF/10V  [C0402]
D12  BAT54C  [SOT23]
D13  LED Red  [D0603_LED]
J3  HEADER2 2.54mm  [SIP2M_2D54]
L2  2.2uH/1.5A-2016  [L2016]
L3  1uH/2.7A  [L2016]
L4  1uH/2.7A  [L2016]
L5  1uH/2.7A  [L2016]
L6  1uH/2.7A  [L2016]
L8  2.2uH/1.5A-2016  [L2016]
Q1  WPM3401  [SOT23]
Q2  MMBT3904  [SOT23]
R13  0R-0603  [R0603]
R14  0R-0603  [R0603]
R15  100K  [R0402]
R16  1M/1%  [R0402]
R17  499K/1%  [R0402]
R18  0R-0603  [R0603]
R19  0R-0603  [R0603]
R20  0R-0603  [R0603]
R21  100K  [R0402]
R22  100K  [R0402]
R23  1M/1%  [R0402]
R25  1M/1%  [R0402]
R26  100K  [R0402]
R28  221K/1%  [R0402]
R29  499K/1%  [R0402]
R30  0R-0603  [R0603]
R31  0R-0603  [R0603]
R32  100K  [R0402]
R33  750K/1%  [R0402]
R34  100K  [R0402]
R35  249K/1%  [R0402]
R36  499K/1%  [R0402]
R37  750K/1%  [R0402]
R54  0R-0603  [R0603]
R91  1M/1%  [R0402]
R93  0R-0603  [R0603]
R96  620K/1%  [R0402]
R173  0R-0603  [R0603]
R208  100K  [R0402]
R231  1M  [R0402]
R232  1M  [R0402]
R233  4.7K  [R0402]
R234  1K  [R0402]
T1  MechanicalHole  [MHOLE_5D5P3D2H]
T2  MechanicalHole  [MHOLE_5D5P3D2H]
T3  MechanicalHole  [MHOLE_5D5P3D2H]
T4  MechanicalHole  [MHOLE_5D5P3D2H]
TP4  1mm_SMD  [TEST_SMD]
TP5  1mm_SMD  [TEST_SMD]
TP6  1mm_SMD  [TEST_SMD]
TP7  1mm_SMD  [TEST_SMD]
TP8  1mm_SMD  [TEST_SMD]
TP9  1mm_SMD  [TEST_SMD]
TP35  1mm_SMD  [TEST_SMD]
U2  ETA3425D2G  [DFN6_0D65_ETA3425]
U3  MP1601GTF-18  [SOT563]
U4  MP1601GTF-18  [SOT563]
U5  MP1601GTF-18  [SOT563]
U6  ETA3425D2G  [DFN6_0D65_ETA3425]
U14  MP1605GTF  [SOT563]
sheet PAGE05_T41_POWER
C37  10uF/6.3V  [C0402_E]
C38  10uF/6.3V  [C0402_E]
C39  100nF/6.3V  [C0402]
C40  100nF/6.3V  [C0402]
C41  10nF/6.3V  [C0402]
C42  100nF/6.3V  [C0402]
C43  100nF/6.3V  [C0402]
C44  1uF/6.3V  [C0402]
C46  10uF/6.3V  [C0402_E]
C47  10uF/6.3V  [C0402_E]
C48  10uF/6.3V  [C0402_E]
C49  10uF/6.3V  [C0402_E]
C50  100nF/6.3V  [C0402]
C51  100nF/6.3V  [C0402]
C52  100nF/6.3V  [C0402]
C53  100nF/6.3V  [C0402]
C54  10nF/6.3V  [C0402]
C55  10nF/6.3V  [C0402]
C56  10nF/6.3V  [C0402]
C57  10nF/6.3V  [C0402]
C58  10uF/6.3V  [C0402_E]
C129  100nF/6.3V  [C0402]
C130  100nF/6.3V  [C0402]
C131  100nF/6.3V  [C0402]
C132  10nF/6.3V  [C0402]
C133  1uF/6.3V  [C0402]
C134  100nF/6.3V  [C0402]
FB2  1000ohm/250mA  [FB0402]
R116  240R/1%  [R0402]
R117  240R/1%  [R0402]
R118  10K/1%  [R0402]
R119  10K/1%  [R0402]
sheet PAGE06_T41_SYS_APeripheral
C59  1uF/6.3V  [C0402]
C60  100nF/6.3V  [C0402]
C61  100nF/25V  [C0402]
C62  4.7uF/6.3V  [C0402]
C63  4.7uF/6.3V  [C0402]
C64  100nF/25V  [C0402]
C65  100nF/25V  [C0402]
C66  12pF/50V  [C0402]
C67  12pF/50V  [C0402]
C68  4.7uF/6.3V  [C0402]
C69  100nF/25V  [C0402]
C70  100nF/25V  [C0402]
C71  18pF/50V  [C0402]
C72  18pF/50V  [C0402]
C73  1uF/6.3V  [C0402]
C74  100nF/6.3V  [C0402]
C135  1uF/6.3V  [C0402]
C136  100nF/6.3V  [C0402]
C137  1uF/6.3V  [C0402]
C138  100nF/6.3V  [C0402]
C139  1uF/6.3V  [C0402]
C140  100nF/6.3V  [C0402]
C141  4.7uF/6.3V  [C0402]
C142  100nF/6.3V  [C0402]
C143  100nF/6.3V  [C0402]
C169  100nF/6.3V  [C0402]
C176  1uF/6.3V  [C0402]
C177  100nF/6.3V  [C0402]
FB3  1000ohm/250mA  [FB0402]
FB4  1000ohm/250mA  [FB0402]
FB5  1000ohm/250mA  [FB0402]
FB6  1000ohm/250mA  [FB0402]
FB7  1000ohm/250mA  [FB0402]
FB8  1000ohm/250mA  [FB0402]
R24  10K/1%  [R0402]
R27  15K/1%  [R0402]
R41  1M  [R0402]
R43  33R  [R0402]
R44  100K  [R0402]
R52  1M  [R0402]
R55  1K  [R0402]
R120  33R  [R0402]
R121  1K  [R0402]
R122  1K  [R0402]
R216  4.7R/5%  [R0402]
TP12  1mm_SMD  [TEST_SMD]
TP13  1mm_SMD  [TEST_SMD]
TP14  1mm_SMD  [TEST_SMD]
TP15  1mm_SMD  [TEST_SMD]
TP16  1mm_SMD  [TEST_SMD]
U8  MX25L12833F  [WSOP8_1D27]
Y1  24M  [CRY_2D5X2D0]
Y3  32.768KHz  [CRY_3D2X1D5]
sheet PAGE08_T41_INTERFACE02
U7  T41 BGA232  [BGA232_0D65_T41]  (sections A,B,C,D)
sheet PAGE09_SD_AUDIO_EMMC
C75  3.3nF/50V  [C0402]
C76  3.3nF/50V  [C0402]
C77  10uF/6.3V  [C0402_E]
C78  100pF/50V  [C0402]
C79  10uF/6.3V  [C0402_E]
C80  4.7uF/6.3V  [C0402]
C81  100nF/25V  [C0402]
C82  100nF/6.3V  [C0402]
C83  10uF/6.3V  [C0402_E]
C84  100nF/25V  [C0402]
C85  4.7uF/6.3V  [C0402]
C87  10uF/6.3V  [C0402_E]
C88  100nF/6.3V  [C0402]
C89  10uF/6.3V  [C0402_E]
C90  100nF/6.3V  [C0402]
C91  8.2pF/50V  [C0402]
C92  1uF/6.3V  [C0402]
C93  1uF/6.3V  [C0402]
D6  ESD5451X  [ESD0402]
D7  ESD5451X  [ESD0402]
D8  ESD5451X  [ESD0402]
D9  ESD5451X  [ESD0402]
D15  ESD5451X  [ESD0402]
FB1  220ohm/1.4A  [FB0402]
FB11  220ohm/1.4A  [FB0402]
J5  CON2 1.25mm LT  [CON2-1D25-LT]
J6  MICROSD_TF  [TFCARD]
J7  CON2 1.25mm LT  [CON2-1D25-LT]
Q3  WPM3401  [SOT23]
R56  0R-0603  [R0603]
R57  0R-0603  [R0603]
R58  100K  [R0402]
R59  68K/1%  [R0402]
R60  68K/1%  [R0402]
R61  100K  [R0402]
R62  100K  [R0402]
R63  100K  [R0402]
R64  100K  [R0402]
R65  100K  [R0402]
R66  100K  [R0402]
R67  1.1K  [R0402]
R68  100K  [R0402]
R69  1.1K  [R0402]
R70  10K  [R0402]
R71  10K  [R0402]
R72  10K  [R0402]
R73  10K  [R0402]
R74  10K  [R0402]
R75  10K  [R0402]
R76  10K  [R0402]
R77  10K  [R0402]
R78  10K  [R0402]
R79  100K  [R0402]
R80  1.1K  [R0402]
R81  1.1K  [R0402]
R82  0R  [R0402]
R83  0R  [R0402]
R84  0R  [R0402]
R85  0R  [R0402]
R86  0R  [R0402]
R87  0R  [R0402]
R88  10K  [R0402]
R131  0R  [R0402]
R132  0R  [R0402]
R133  0R  [R0402]
R134  0R  [R0402]
R135  0R  [R0402]
R136  0R  [R0402]
R137  0R  [R0402]
TP33  0.5mm_SMD  [TEST_SMD_0D5]
U10  CS8302M  [MSOP8_0D65]
U11  FEMDNN008G-08A39  [BGA153_0D5_FEMDNN008G]  (section A)
sheet PAGE11_MIPI_DVP_CAMERA
C101  100nF/6.3V  [C0402]
C102  100nF/6.3V  [C0402]
C107  10uF/6.3V  [C0402_E]
D14  940nm IRLED  [DIP2_2D54_LED]
D16  940nm IRLED  [DIP2_2D54_LED]
H1  MHOBL  [MHOLE_3D0X2D0]
H2  MHOBL  [MHOLE_3D0X2D0]
H3  MHOBL  [MHOLE_3D0X2D0]
J10  CON36 0.5mm LT  [FPC-CON36-0D5-LT]
J11  CON30 0.5mm LT  [FPC-CON30-0D5-LT]
Q8  WPM3401  [SOT23]
R99  0R-0603  [R0603]
R100  0R  [R0402]
R101  0R  [R0402]
R102  0R  [R0402]
R103  0R  [R0402]
R104  0R  [R0402]
R105  0R  [R0402]
R106  0R  [R0402]
R107  0R  [R0402]
R108  0R  [R0402]
R109  0R  [R0402]
R110  0R  [R0402]
R124  0R  [R0402]
R125  0R  [R0402]
R126  0R  [R0402]
R127  0R-0603  [R0603]
R128  0R-0603  [R0603]
R129  0R-0603  [R0603]
R159  10R/1%-1206  [R1206]
R165  10K  [R0402]
R167  100K  [R0402]
TP10  1mm_SMD  [TEST_SMD]
TP18  0.5mm_SMD  [TEST_SMD_0D5]
TP19  1mm_SMD  [TEST_SMD]
TP20  1mm_SMD  [TEST_SMD]
TP21  0.5mm_SMD  [TEST_SMD_0D5]
TP22  1mm_SMD  [TEST_SMD]
TP23  0.5mm_SMD  [TEST_SMD_0D5]
TP24  0.5mm_SMD  [TEST_SMD_0D5]
TP25  0.5mm_SMD  [TEST_SMD_0D5]
TP26  0.5mm_SMD  [TEST_SMD_0D5]
TP27  0.5mm_SMD  [TEST_SMD_0D5]
TP28  0.5mm_SMD  [TEST_SMD_0D5]
TP29  0.5mm_SMD  [TEST_SMD_0D5]
TP30  0.5mm_SMD  [TEST_SMD_0D5]
TP31  0.5mm_SMD  [TEST_SMD_0D5]
TP32  1mm_SMD  [TEST_SMD]
sheet PAGE15_KEY_LED_RTC_BOOT
C86  1uF/6.3V  [C0402]
C94  1uF/6.3V  [C0402]
C95  100nF/6.3V  [C0402]
C97  10nF/6.3V  [C0402]
C98  10uF/6.3V-0603  [C0603]
C99  1uF/6.3V  [C0402]
C100  10nF/6.3V  [C0402]
C158  18pF/50V  [C0402]
C159  18pF/50V  [C0402]
C181  100nF/6.3V  [C0402]
D10  ESD5451X  [ESD0402]
D11  LED RGB CC  [D0603_LED3_CC]
R89  100K  [R0402]
R90  100K  [R0402]
R94  1K  [R0402]
R95  1K  [R0402]
R97  0R  [R0402]
R140  4.7K  [R0402]
R141  10K  [R0402]
R142  100K  [R0402]
R152  4.7K  [R0402]
R153  10K  [R0402]
R270  100K  [R0402]
R271  100K  [R0402]
R272  100K  [R0402]
SW1  KEY2_SMD  [SW2_SMD]
SW2  KEY2_SMD  [SW2_SMD]
SW3  KEY2_SMD  [SW2_SMD]
TP34  1mm_SMD  [TEST_SMD]
TP36  1mm_SMD  [TEST_SMD]
U12  SGM2019-1.8YN5G  [SOT23-5]
U13  SGM2036-0.8YN5G  [SOT23-5]
U21  BM8563ESA  [SOP8_1D27_BM8563]
Y2  32.768KHz  [CRY_3D2X1D5]

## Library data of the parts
C10 C12 C14 C16 C20 C26 C30 C37 C38 C46-C49 C58 C77 C79 C83 C87 C89 C164 C166 C168 = CAP: Capacitor-10uF,+/-20%,X5R,6.3V-0402+; Part Number: 02.0034.00; Part Type: 0402表贴普通电容; 供应商: YAGEO / Murata; 规格型号1: CC0402MRX5R5BB106 / GRM155R60J106ME44D; 联系人: 谢苏云; 手机: 15900554174; 邮箱: susan.xie@murata.com
C11 C13 C15 C17 C19 C21 C23 C27 C29 C31 C33 C96 C108 C165 C167 C205 C206 = CAP: Capacitor-100nF,+/-10%,X7R,10V-0402; Part Number: 02.0075.00; Part Type: 0402表贴普通电容; 供应商: Murata; 供应商1: Eyang; 规格型号1: GRM155R71A104KA01D; 联系人: 谢苏云; 联系人1: 何俊; 手机: 15900554174; 手机1: 18317187178; 邮箱: susan.xie@murata.com; 邮箱1: hejunxs@szeyang.com
C18 C22 C28 C32 = CAP: Capacitor-22uF,+/-20%,X5R,10V-0603，不推荐（替代料不好寻）; Part Number: 02.0039.00; Part Type: 0603表贴普通电容; 供应商: Murata; 规格型号1: GRM188R61A226ME15D; 联系人: 谢苏云; 手机: 15900554174; 邮箱: susan.xie@murata.com
C24 C25 C34 C35 = CAP: Capacitor-22pF,+/-5%,C0G,50V-0402; Part Number: 02.0008.00; Part Type: 0402表贴普通电容; 供应商: YAGEO / Murata; 规格型号1: CC0402JRNPO9BN220 / GRM1552C1H220JA01D; 联系人: 谢苏云; 手机: 15900554174; 邮箱: susan.xie@murata.com
D12 = DIODE_CA3: General Semi BAT54C Two channel Schottky Barrier Diode; Part Number: 09.0020.00; Part Type: 二极管; Datasheet: BAT54C.pdf
D13 = LED_1: Part Number: 09.0003.00; Part Type: 发光二极管; 规格型号1: 0603贴片红灯; Datasheet: 0603_LED.PDF
J3 = HEADER2X1: HEADER 2X1 2.54mm MALE; Part Number: 04.0031.00; Part Type: 2.54mm单排插针; 规格型号1: 2.54mm 1X2单排插针
L2 L8 = INDUCTOR: MuRata DFE201612P-2R2MS=P2 2.2uH/1.5A-2016 POWER INDUCTOR; Part Number: 03.0022.00; Part Type: 2016表贴电感; 供应商: Murata; 规格型号1: DFE201612P-2R2MS=P2; 联系人: 谢苏云; 手机: 15900554174; 邮箱: susan.xie@murata.com; Datasheet: DFE201612P_Murata data sheet_170130.pdf
L3-L6 = INDUCTOR: Murata DFE201612P-1R0M=P2 1uH/2.7A（Tr=40）±20% H=1.2mm POWER INDUCTOR; Part Number: 03.0035.00; Part Type: 2016表贴电感; 供应商: Murata; 规格型号1: DFE201612P-1R0M=P2; 联系人: 谢苏云; 手机: 15900554174; 邮箱: susan.xie@murata.com; Datasheet: DFE201612P_Murata data sheet_170130.pdf
Q1 Q3 Q8 = P_MOS: WILL WPM3401 P-Channel MOSFET; Part Number: 09.0008.00; Part Type: MOS管; 供应商: Will; 联系人: 安志鹏; 手机: 18321800431; 邮箱: an.zhipeng@sh-willsemi.com; Datasheet: WPM340_datasheet.pdf
Q2 = NPN: MMBT3904 NPN General Purpose Transistor; Part Number: 09.0007.00; Part Type: 三极管; Datasheet: MMBT3904.pdf
R13 R14 R18-R20 R30 R31 R54 R56 R57 R93 R99 R127-R129 R173 = RES: Resistor-0R,+/-5%,1/10W-0603; Part Number: 01.0051.00; Part Type: 0603表贴普通电阻; 供应商: 厚声; 规格型号1: 0603WAJ0000T5E
R15 R21 R22 R26 R32 R34 R44 R58 R61-R66 R68 R79 R89 R90 R142 R167 R208 R270-R272 = RES: Resistor-100K,+/-5%,1/16W-0402; Part Number: 01.0041.00; Part Type: 0402表贴普通电阻; 供应商: 厚声; 规格型号1: 0402WGJ0104TCE
R16 R23 R25 R91 = RES: Resistor-1M,+/-1%,1/16W-0402; Part Number: 01.0048.00; Part Type: 0402表贴高精度电阻; 供应商: 厚声; 规格型号1: 0402WGF1004TCE
R17 R29 R36 = RES: Resistor-499K,+/-1%,1/16W-0402; Part Number: 01.0116.00; Part Type: 0402表贴高精度电阻; 供应商: 厚声; 规格型号1: 0402WGF4993TCE
R28 = RES: Resistor-221K,+/-1%,1/16W-0402; Part Number: 01.0115.00; Part Type: 0402表贴高精度电阻; 供应商: 厚声; 规格型号1: 0402WGF2213TCE
R33 R37 = RES: Resistor-750K,+/-1%,1/16W-0402; Part Number: 01.0096.00; Part Type: 0402表贴高精度电阻; 供应商: 厚声; 规格型号1: 0402WGF7503TCE
R35 = RES: Resistor-249K,+/-1%,1/16W-0402; Part Number: 01.0102.00; Part Type: 0402表贴高精度电阻; 供应商: 厚声; 规格型号1: 0402WGF2493TCE
R96 = RES: Resistor-620K,+/-1%,1/16W-0402; Part Number: 01.0119.00; Part Type: 0402表贴高精度电阻; 供应商: 厚声; 规格型号1: 0402WGF6203TCE
R41 R231 R232 = RES: Resistor-1M,+/-5%,1/16W-0402; Part Number: 01.0049.00; Part Type: 0402表贴普通电阻; 供应商: 厚声; 规格型号1: 0402WGJ0105TCE
R233 = RES: Resistor-4.7K,+/-5%,1/16W-0402; Part Number: 01.0019.00; Part Type: 0402表贴普通电阻; 供应商: 厚声; 规格型号1: 0402WGJ0472TCE
R55 R94 R95 R121 R122 R234 = RES: Resistor-1K,+/-5%,1/16W-0402; Part Number: 01.0014.00; Part Type: 0402表贴普通电阻; 供应商: 厚声; 规格型号1: 0402WGJ0102TCE
T1-T4 = MHOLE2: MechanicalHole φ5.5mm Drill 3.2mm With 8 GND Vias; Part Number: AB.0002.00
TP4-TP10 TP12-TP16 TP19 TP20 TP22 TP32 TP34-TP36 = TP: SMD Test Point φ1mm; Part Number: AA.0001.00; Part Type: Test Point
U2 U6 = ETA3425: ETA ETA3425 0.6A 1.2MHz Input-2.6V~7V Buck Regulator; Part Number: 05.2025.00; Part Type: 降压型DCDC; 供应商: ETA; 联系人: 徐卓荣; 手机: 13923780263; 邮箱: xuzhuorong@etasolution.com; Datasheet: ETA3425_V3.1.pdf
U3-U5 = MP160x: MPS MP1601GTF-18 1A 2.2MHz Input 2.3V~5.5V Buck Converter; Part Number: 05.2012.00; Part Type: 降压型DCDC; 供应商: MPS; 联系人: 孙舒婷; 手机: 17821844882; 邮箱: Susan.Sun@monolithicpower.com; Datasheet: MP1601_r0.82.pdf
U14 = MP160x: MPS MP1605GTF 2A 2.2MHz Input 2.3V~5.5V Buck Converter; Part Number: 05.2013.00; Part Type: 降压型DCDC; 供应商: MPS; 联系人: 孙舒婷; 手机: 17821844882; 邮箱: Susan.Sun@monolithicpower.com; Datasheet: MP1605_r0.8.pdf
C39 C40 C42 C43 C50-C53 C60 C74 C82 C88 C90 C95 C101 C102 C129-C131 C134 C136 C138 C140 C142 C143 C169 C177 C181 = CAP: Capacitor-100nF,+/-10%,X7R,6.3V-0402; Part Number: 02.0075.00; Part Type: 0402表贴普通电容; 供应商: Murata; 规格型号1: GRM155R70J104KA01D; 联系人: 谢苏云; 手机: 15900554174; 邮箱: susan.xie@murata.com
C41 C54-C57 C97 C100 C132 = CAP: Capacitor-10nF,+/-10%,X7R,6.3V-0402; Part Number: 02.0075.00; Part Type: 0402表贴普通电容; 供应商: Murata; 规格型号1: GRM155R70J102KA01D; 联系人: 谢苏云; 手机: 15900554174; 邮箱: susan.xie@murata.com
C44 C59 C73 C86 C92-C94 C99 C133 C135 C137 C139 C176 = CAP: Capacitor-1uF,+/-10%,X7R,6.3V-0402; Part Number: 02.0076.00; Part Type: 0402表贴普通电容; 供应商: Murata; 规格型号1: GRM155R70J105KA12; 联系人: 谢苏云; 手机: 15900554174; 邮箱: susan.xie@murata.com
FB2-FB8 = BEAD: Murata BLM15HG102SN1D Z=1000ohm@100MHz 250mA 1.1ohm 25%; Part Number: 03.1001.00; Part Type: 0402表贴磁珠; 供应商: Murata; 规格型号1: BLM15HG102SN1D; 联系人: 谢苏云; 手机: 15900554174; 邮箱: susan.xie@murata.com; Datasheet: BLM15HG.pdf
R116 R117 = RES: Resistor-240R,+/-1%,1/16W-0402; Part Number: 01.0010.00; Part Type: 0402表贴高精度电阻; 供应商: 厚声; 规格型号1: 0402WGF2400TCE
R24 R118 R119 = RES: Resistor-10K,+/-1%,1/16W-0402; Part Number: 01.0024.00; Part Type: 0402表贴高精度电阻; 供应商: 厚声; 规格型号1: 0402WGF1002TCE
C61 C64 C65 C69 C81 C84 = CAP: Capacitor-100nF,+/-10%,X5R,25V-0402; Part Number: 02.0038.00; Part Type: 0402表贴普通电容; 供应商: YAGEO / Murata; 规格型号1: CC0402KRX5R8BB104 / GRM155R71E104KE14D; 联系人: 谢苏云; 手机: 15900554174; 邮箱: susan.xie@murata.com
C62 C63 C68 C80 C85 C141 = CAP: Capacitor-4.7uF,+/-20%,X5R,6.3V-0402; Part Number: 02.0018.00; Part Type: 0402表贴普通电容; 供应商: YAGEO / Murata; 规格型号1: CC0402MRX5R5BB475 / GRM153R60J475ME15D; 联系人: 谢苏云; 手机: 15900554174; 邮箱: susan.xie@murata.com
C66 C67 = CAP: Capacitor-12pF,+/-5%,C0G,50V-0402; ID: 8; Part Number: 02.0006.00; Part Type: 0402表贴普通电容; 供应商: YAGEO / Murata; 供应商2: Murata; 规格型号1: CC0402JRNPO9BN120 / GCM1555C1H120JA16D; 联系人: 谢苏云; 联系人2: 吴铭; 手机: 15900554174; 手机2: 13761466262; 邮箱: susan.xie@murata.com; 邮箱2: cherry.wu@murata.com
C70 = CAP: Capacitor-100nF,+/-10%,X5R,25V-0402; ID: 15; Part Number: 02.0038.00; Part Type: 0402表贴普通电容; 供应商: YAGEO / Murata; 供应商1: Eyang; 规格型号1: CC0402KRX5R8BB104 / GRM155R71E104KE14D; 联系人: 谢苏云; 联系人1: 何俊; 手机: 15900554174; 手机1: 18317187178; 邮箱: susan.xie@murata.com; 邮箱1: hejunxs@szeyang.com
C71 C72 C158 C159 = CAP: Capacitor-18pF,+/-2%,C0G,50V-0402; Part Number: 02.0049.00; Part Type: 0402表贴普通电容; 供应商: YAGEO / Murata; 规格型号1: CC0402GRNPO9BN180 / GRM1555C1H180GA01D; 联系人: 谢苏云; 手机: 15900554174; 邮箱: susan.xie@murata.com
R27 = RES: Resistor-15K,+/-1%,1/16W-0402; Part Number: 01.0024.00; Part Type: 0402表贴高精度电阻; 供应商: 厚声; 规格型号1: 0402WGF1502TCE
R43 R120 = RES: Resistor-33R,+/-5%,1/16W-0402; Part Number: 01.0005.00; Part Type: 0402表贴普通电阻; 供应商: 厚声; 规格型号1: 0402WGJ0330TCE
R52 = RES: Resistor-1M,+/-5%,1/16W-0402; ID: 49; Part Number: 01.0049.00; Part Type: 0402表贴普通电阻; 供应商: 厚声; 供应商1: Eyang; 规格型号1: 0402WGJ0105TCE; 联系人1: 何俊; 手机1: 18317187178; 邮箱1: hejunxs@szeyang.com
R216 = RES: Resistor-4.7R,+/-5%,1/16W-0402; Part Number: 01.0126.00; Part Type: 0402表贴普通电阻; 供应商: 厚声; 规格型号1: 0402WGJ470TCE
U8 = SPI_NOR: MACRONIX MX25L12833F 3V 128Mbit CMOS MXSMIO SPI NOR FLASH MEMORY; Part Number: 06.0015.02; Part Type: SPI NOR; 供应商: 旺宏; 联系人: 李永坚; 手机: 13646217175; 邮箱: jamesli01@mxic.com.cn; Datasheet: MX25L12833F, 3V, 128Mb, v1.0.pdf
Y1 = XTAL_P4: Murata XRCGB24M000F3M01R0 initial ±30ppm CL=8pF Crystal; Part Number: 08.0026.00; Part Type: Crystal; 供应商: Murata; 规格型号1: XRCGB24M000F3M01R0; 联系人: 谢苏云; 手机: 15900554174; 邮箱: susan.xie@murata.com; Datasheet: XRCGB24M000F3M01R0.pdf
Y2 Y3 = XTAL_P2: MICRO Crystal CM7V-T1A Crystal 32.768KHz 12.5pF; Part Number: 08.0016.00; Part Type: Crystal; 供应商: MicroCrystal; 规格型号1: CM7V-T1A; 联系人: 郑蓓蓓; 手机: 13482156565; 邮箱: Sherry.Zheng@cn.swatchgroup.com; Datasheet: CM7V-T1A.pdf
U7 = T41_BGA232: Ingenic T41 Smart Video Processor FBGA 232Ball 0.65mmPitch 11mmX11mm; Part Number: 06.0137.00; Part Type: CPU; 供应商: Ingenic; 规格型号1: T41
C75 C76 = CAP: Capacitor-3.3nF,+/-10%,X7R,50V-0402; Part Number: 02.0042.00; Part Type: 0402表贴普通电容; 供应商: YAGEO / Murata; 规格型号1: CC0402KRX7R9BB332 / GRM155R71H332KA01D; 联系人: 谢苏云; 手机: 15900554174; 邮箱: susan.xie@murata.com
C78 = CAP: Capacitor-100pF,+/-5%,C0G,50V-0402; Part Number: 02.0059.00; Part Type: 0402表贴普通电容; 供应商: YAGEO / Murata; 规格型号1: CC0402JRNPO9BN101 / GCM1555C1H101JA16D; 联系人: 谢苏云; 手机: 15900554174; 邮箱: susan.xie@murata.com
C91 = CAP: Capacitor-8.2pF,+/-0.25pF,C0G,50V-0402; Part Number: 02.0047.00; Part Type: 0402表贴普通电容; 供应商: YAGEO / Murata; 规格型号1: CC0402CRNPO9BN8R2 / GRM1555C1H8R2CA01D; 联系人: 谢苏云; 手机: 15900554174; 邮箱: susan.xie@murata.com
D6-D10 D15 = ESD: WILL ESD5451X-2/TR Bidirection 17.5pF Transient Voltage Suppressor; Part Number: 09.0006.00; 供应商: Will; 规格型号1: ESD5451X-2/TR; 联系人: 安志鹏; 手机: 18321800431; 邮箱: an.zhipeng@sh-willsemi.com; Datasheet: ESD5451X.pdf
FB1 FB11 = BEAD: Murata BLM15PX221SN1D Z=220ohm@100MHz 1.4A 0.1ohm 25%; Part Number: 03.1006.00; Part Type: 0402表贴磁珠; 供应商: Murata; 规格型号1: BLM15PX221SN1D; 联系人: 谢苏云; 手机: 15900554174; 邮箱: susan.xie@murata.com; Datasheet: BLM15.pdf
J5 J7 = CON_2X1: HOLY 1.25mm Pitch 2P LT SMD Connector; Part Number: 04.0001.00; Part Type: 1.25mm立贴连接器; 供应商: 深圳宏利电子; 规格型号1: 1.25mm立贴2P插座; 联系人: 谢素平; 手机: 16717558767; Datasheet: 1.25mm 立贴.pdf
J6 = MMC_SD: TF CARD SOCKET; Part Number: 10.0003.00; Part Type: TF Card; 规格型号1: TF卡座; Datasheet: TF卡座.jpg
R59 R60 = RES: Resistor-68K,+/-1%,1/16W-0402; Part Number: 01.0038.00; Part Type: 0402表贴高精度电阻; 供应商: 厚声; 规格型号1: 0402WGF6802TCE
R67 R69 R80 R81 = RES: Resistor-1.1K,+/-5%,1/16W-0402; Part Number: 01.0149.00; Part Type: 0402表贴普通电阻; 供应商: 厚声; 规格型号1: 0402WGJ0112TCE
R70-R78 R88 R141 R153 R165 = RES: Resistor-10K,+/-5%,1/16W-0402; Part Number: 01.0023.00; Part Type: 0402表贴普通电阻; 供应商: 厚声; 规格型号1: 0402WGJ0103TCE
R82-R87 R97 R100-R110 R124-R126 R131-R137 = RES: Resistor-0R,+/-5%,1/16W-0402; Part Number: 01.0001.00; Part Type: 0402表贴普通电阻; 供应商: 厚声; 规格型号1: 0402WGJ0000TCE
TP18 TP21 TP23-TP31 TP33 = TP: SMD Test Point φ0.5mm; Part Number: AA.0006.00; Part Type: Test Point
U10 = CS8302: 上海智浦欣 CS8302M 3W 单声道 超低EMI 无滤波器 D类音频功放; Part Number: 06.0105.00; Part Type: 功放芯片; 供应商: 芯晶图电子; 联系人: 费军; 手机: 13808850029; 邮箱: eric.fei@shinychip.com; Datasheet: CS8302M_ch_v1.0.pdf
U11 = FEMDNN008G: FORESEE FEMDNN008G-08A39 8GB 8xIOs e-MMC 153Ball 0.5mmPitch; Part Number: 06.0145.00; Part Type: EMMC; 供应商: FORESEE; 联系人: 徐洪波; 手机: 18565783127; 邮箱: hongbo.xu@longsys.com; Datasheet: eMMC_FORESEE_FEMDNN008G-08A39_SPEC_20200228.pdf
C107 = CAP: Capacitor-10uF,+/-20%,X5R,6.3V-0402+; Part Number: 02.0034.00; Part Type: 0402表贴普通电容; 供应商: YAGEO / Murata; 供应商2: Murata; 规格型号1: CC0402MRX5R5BB106 / GRM155R60J106ME44D; 联系人: 谢苏云; 联系人2: 吴铭; 手机: 15900554174; 手机2: 13761466262; 邮箱: susan.xie@murata.com; 邮箱2: cherry.wu@murata.com
D14 D16 = LED_1: IR LED F5mm 940nm; Part Number: 09.0024.00; Part Type: 红外LED; 规格型号1: 940nm直插红外灯; Datasheet: IRLED.jpg
H1-H3 = MHOLE1: MechanicalHole φ4.2mmX3.2mm Drill 3.0mmX2.0mm; Part Number: AB.0001.00; Part Type: MechanicalHole
J10 = FPCCON_18X2: HOLY 0.5mm pitch FPC LT 36 Pin Connector; Part Number: 04.0014.00; Part Type: 0.5mm立贴FPC连接器; 供应商: 深圳宏利电子; 规格型号1: FPC0.5mm-36P立贴正位; 联系人: 谢素平; 手机: 16717558767; Datasheet: 0.5mm立式正位全包.pdf
J11 = FPCCON_15x2: HOLY 0.5mm pitch FPC LT 30 Pin Connector; Part Number: 04.0011.00; Part Type: 0.5mm立贴FPC连接器; 供应商: 深圳宏利电子; 规格型号1: FPC0.5mm-30P立贴正位; 联系人: 谢素平; 手机: 16717558767; Datasheet: 0.5mm立式正位全包.pdf
R159 = RES: Resistor-10R,+/-1%,1/4W-1206; Part Number: 01.0074.00; Part Type: 1206表贴高精度电阻; 供应商: 厚声; 规格型号1: 1206W4J0100T5E
C98 = CAP: Capacitor-10uF,+/-20%,X5R,6.3V-0603; Part Number: 02.0026.00; Part Type: 0603表贴普通电容; 供应商: Murata; 规格型号1: GRM188R60J106ME47D; 联系人: 谢苏云; 手机: 15900554174; 邮箱: susan.xie@murata.com
D11 = LED_3C: LED Red Blue Green common cathode; Part Number: 09.0022.00; Part Type: 发光二极管; 规格型号1: 0603RGB 共阴LED; Datasheet: 0603RGB【共阴】.pdf
R140 R152 = RES: Resistor-4.7K,+/-5%,1/16W-0402; ID: 23; Part Number: 01.0019.00; Part Type: 0402表贴普通电阻; 供应商: 厚声; 供应商1: Eyang; 规格型号1: 0402WGJ0472TCE; 联系人1: 何俊; 手机1: 18317187178; 邮箱1: hejunxs@szeyang.com
SW1-SW3 = PUSHBUTTON: PUSHBUTTON 3mmX6mm 2Pin; Part Number: 04.1001.00; Part Type: 按键; 供应商: 深圳旺科达; 规格型号1: TS-020A/4.3A; 联系人: 童国相; 手机: 13824380089; 邮箱: wangkeda2008@163.com
U12 = SGM2019: SGMICRO SGM2019-1.8 300mA Input 2.5V~5.5V LDO Regulator; Part Number: 05.0009.00; Part Type: LDO; 供应商: SGMICRO; 规格型号1: SGM2019-1.8YN5G/TR; 联系人: 王哲; 手机: 18406666893; 邮箱: jayden_wang@sg-micro.com; Datasheet: SGM2019 Series.pdf
U13 = SGM2036: SGMICRO SGM2036-0.8 300mA Input 1.6V~5.5V RF LDO Regulator; Part Number: 05.0018.00; Part Type: LDO; 供应商: SGMICRO; 规格型号1: SGM2036-0.8YN5G/TR; 联系人: 王哲; 手机: 18406666893; 邮箱: jayden_wang@sg-micro.com; Datasheet: SGM2036 REV.A.4_20151123.pdf
U21 = BM8563: 上海贝岭 BM8563 高精度低功耗实时时钟芯片; Part Number: 06.0141.00; Part Type: RTC芯片; 供应商: 芯晶图（代理）; 手机: 13808850029; 邮箱: eric.fei@; Datasheet: BM8563_V1.1_cn.pdf

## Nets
1V8: C22.1 C23.1 C25.1 L4.2 R20.2 R23.2 R55.2 TP7.1 U4.6(OUT) ; also on sheet 3
3V3: C18.1 C19.1 C24.1 C70.2 C80.1 C81.1 C82.1 C101.1 C102.1 FB1.1 FB11.1 L3.2 Q3.2(SOURCE) Q8.2(SOURCE) R19.2 R25.2 R44.2 R57.2 R66.1 R88.2 R89.2 R99.2 R129.1 R140.2 R152.2 R153.2 R165.2 R270.2 R271.2 TP6.1 U3.6(OUT) U8.8(VCC) ; also on sheet 1 2 3 4 6
GND: C10.2 C11.2 C12.2 C13.2 C14.2 C16.2 C17.2 C18.2 C19.2 C20.2 C21.2 C22.2 C23.2 C26.2 C27.2 C28.2 C29.2 C30.2 C31.2 C32.2 C33.2 C37.2 C38.2 C39.2 C40.2 C41.2 C43.2 C44.2 C46.2 C47.2 C48.2 C49.2 C50.2 C51.2 C52.2 C53.2 C54.2 C55.2 C56.2 C57.2 C58.2 C59.2 C60.2 C61.2 C62.2 C63.2 C66.1 C67.1 C68.2 C69.2 C70.1 C71.1 C72.1 C73.2 C74.2 C75.2 C77.2 C80.2 C81.2 C83.2 C84.2 C85.2 C86.2 C87.2 C88.2 C89.2 C90.2 C91.2 C92.2 C93.2 C94.2 C95.1 C96.2 C97.2 C98.2 C99.2 C100.2 C101.2 C107.2 C108.2 C129.2 C130.2 C131.2 C132.2 C133.2 C134.2 C135.2 C136.2 C137.2 C138.2 C139.2 C140.2 C141.2 C142.2 C143.2 C158.1 C159.1 C164.2 C165.2 C166.2 C167.2 C168.2 C169.2 C176.2 C177.2 C181.2 C205.2 C206.2 D6.1(ANODE) D7.1(ANODE) D8.1(ANODE) D9.1(ANODE) D10.1(ANODE) D11.4(CATHODE) D13.2(CATHODE) D15.1(ANODE) H1.1(A) H2.1(A) H3.1(A) J3.2 J5.3(S1) J5.4(S2) J6.6(VSS2) J6.10(GND_2) J6.11(GND_1) J6.12(PAD1) J6.13(PAD2) J7.3(S1) J7.4(S2) J10.7 J10.10 J10.15 J10.20 J10.27 J10.29 J10.37(S1) J10.38(S2) J11.1 J11.4 J11.7 J11.10 J11.13 J11.16 J11.21 J11.23 J11.27 J11.31(S1) J11.32(S2) Q2.2(EMITTER) R17.1 R27.2 R28.1 R29.1 R36.1 R37.1 R58.2 R67.2 R68.2 R91.2 R116.1 R117.1 R119.1 R120.1 R122.1 R159.2 R167.2 R232.1 R233.2 R272.1 SW1.1 SW2.2 SW3.1 T1.1 T1.2 T1.3 T1.4 T1.5 T1.6 T1.7 T1.8 T1.9 T2.1 T2.2 T2.3 T2.4 T2.5 T2.6 T2.7 T2.8 T2.9 T3.1 T3.2 T3.3 T3.4 T3.5 T3.6 T3.7 T3.8 T3.9 T4.1 T4.2 T4.3 T4.4 T4.5 T4.6 T4.7 T4.8 T4.9 U2.6(GND_0) U2.7(GND_1) U3.2(GND) U4.2(GND) U5.2(GND) U6.6(GND_0) U6.7(GND_1) U7.C9(DDRPLL_VSSA) U7.G5(PLL_AVSS) U7.G6(VSS1) U7.G7(VSS2) U7.G8(VSS3) U7.G9(VSS4) U7.G10(VSS5) U7.G11(VSS6) U7.G12(VSS7) U7.G13(VSS8) U7.J6(VSS9) U7.J7(VSS10) U7.J8(VSS11) U7.J9(VSS12) U7.J10(VSS13) U7.J11(VSS14) U7.J12(VSS15) U7.K6(VSS16) U7.K7(VSS17) U7.K8(VSS18) U7.K9(VSS19) U7.K10(VSS20) U7.K11(VSS21) U7.K12(VSS22) U7.L6(VSS23) U7.L7(VSS24) U7.L8(VSS25) U7.L9(VSS26) U7.L10(VSS27) U7.L11(VSS28) U7.L12(VSS29) U7.M7(VSS30) U7.M8(VSS31) U7.M9(VSS32) U7.M10(VSS33) U7.M11(VSS34) U7.M12(VSS35) U7.M13(VSS36) U7.N12(VSS37) U7.N13(SADC_AGND) U7.N15(SADC_VIN3) U7.P4(CODEC_AVSS) U7.P16(SADC_VIN2) U7.R17(SADC_VIN1) U8.4(GND) U10.7(GND) U11.A6(VSS_1) U11.C4(VSSQ_1) U11.E7(VSS_2) U11.G5(VSS_3) U11.H10(VSS_4) U11.J5(VSS_5) U11.K8(VSS_6) U11.N2(VSSQ_2) U11.N5(VSSQ_3) U11.P4(VSSQ_4) U11.P6(VSSQ_5) U12.2(GND) U13.2(GND) U14.2(GND) U21.4(GND) Y1.2 Y1.4 ; also on sheet 1 2 3 4 5 6 9
VCC_3V3: C12.1 C13.1 C14.1 C86.1 C166.1 C167.1 C168.1 C181.1 L2.2 L8.2 R13.2 R16.2 R54.2 R93.2 R96.2 R97.1 R141.1 R234.1 TP35.1 U12.1(VIN) U21.8(VDD)
VCC_5V: R24.2 ; also on sheet 1 9
VCC_SOC: C16.1 C17.1 C20.1 C21.1 C26.1 C27.1 C30.1 C31.1 Q1.3(DRAIN) R22.1 R26.1 R32.1 R34.1 R56.2 R127.2 R128.1 TP5.1 U3.3(VIN) U4.3(VIN) U5.3(VIN) U14.3(VIN) ; also on sheet 1
VCC_SYS: R14.1 R18.1 R173.1 ; also on sheet 6 9
VCCQ_3V3: C89.1 C90.1 FB11.2 R70.1 R71.1 R72.1 R73.1 R74.1 R75.1 R76.1 R77.1 R78.1 R79.2 U11.C6(VCCQ_5) U11.M4(VCCQ_1) U11.N4(VCCQ_2) U11.P3(VCCQ_3) U11.P5(VCCQ_4)
VDDMSC0: C83.1 C84.1 D8.2(CATHODE) J6.4(VDD) Q3.3(DRAIN) R61.1 R62.1 R63.1 R64.1 R65.1 R68.1
ADC_AVDD: C73.1 C74.1 FB7.2 U7.N16(SADC_VREFP) U7.N17(SADC_AVDD)
BOOTSEL0: R270.1 SW3.2 U7.A9(BOOT_SEL0_PC00)
BOOTSEL1: R271.1 R272.2 U7.B9(BOOT_SEL1_PC01)
CODEC_AVDD: C61.1 C62.1 FB8.2 U7.R1(CODEC_AVDD)
CSI_CLKN_DVP_D4: R110.1 R124.1 TP26.1 ; also on sheet 5
CSI_CLKP_DVP_D5: R108.1 R109.1 TP25.1 ; also on sheet 5
CSI_DATAN0_DVP_D0: R102.1 R103.1 TP21.1 ; also on sheet 5
CSI_DATAN1_DVP_D2: R106.1 R107.1 TP24.1 ; also on sheet 5
CSI_DATAP0_DVP_D1: R100.1 R101.1 TP18.1 ; also on sheet 5
CSI_DATAP1_DVP_D3: R104.1 R105.1 TP23.1 ; also on sheet 5
DDR_VREF: C42.2 C43.1 R118.1 R119.2 U7.E5(DDR_VREF)
DDRPLL_VCCA: C133.1 C134.1 FB2.1 U7.B8(DDRPLL_VCCA)
DDRVDD: C37.1 C38.1 C39.1 C40.1 C41.1 C42.1 C44.1 C58.1 C129.1 C130.1 C131.1 C132.1 R30.1 R118.2 U7.E6(VDDMEM1) U7.E7(VDDMEM2) U7.E8(VDDMEM3) U7.E9(VDDMEM4) U7.E10(VDDMEM5) U7.E11(VDDMEM6) U7.E12(VDDMEM7) U7.F5(DDRVDD1) U7.F6(DDRVDD2) U7.F7(DDRVDD3) U7.F8(DDRVDD4) U7.F9(DDRVDD5) U7.F10(DDRVDD6) U7.F11(DDRVDD7) U7.F12(DDRVDD8)
DVP_3V3: J10.1 J10.2 R99.1
DVP_5V: J10.34 J10.35 J10.36 R127.1
DVP_D0: J10.11 R103.2
DVP_D1: J10.12 R101.2
DVP_D2: J10.13 R107.2
DVP_D3: J10.14 R105.2
DVP_D4: J10.16 R124.2
DVP_D5: J10.17 R109.2
DVP_D6: J10.18 ; also on sheet 5
DVP_D7: J10.19 ; also on sheet 5
DVP_D8: J10.21 ; also on sheet 5
DVP_D9: J10.22 ; also on sheet 5
DVP_HSYNC: J10.8 TP20.1 ; also on sheet 5
DVP_MCLK_PA15: J10.28 R126.2 TP10.1
DVP_PCLK: J10.26 TP19.1 ; also on sheet 5
DVP_VSYNC: J10.9 TP22.1 ; also on sheet 5
EMMC_3V3: C87.1 C88.1 FB1.2 U11.E6(VCC_1) U11.F5(VCC_2) U11.J10(VCC_3) U11.K9(VCC_4)
EMMC_D4: R74.2 U11.B3(DAT4)
EMMC_D5: R75.2 U11.B4(DAT5)
EMMC_D6: R76.2 U11.B5(DAT6)
EMMC_D7: R77.2 U11.B6(DAT7)
EMMC_DS: TP33.1 U11.H5(DS)
EMMC_MSC0_CLK: C91.1 R86.2 U11.M6(CLK)
EMMC_MSC0_CMD: R78.2 R84.2 U11.M5(CMD)
EMMC_MSC0_D0: R70.2 R131.2 U11.A3(DAT0)
EMMC_MSC0_D1: R71.2 R133.2 U11.A4(DAT1)
EMMC_MSC0_D2: R72.2 R135.2 U11.A5(DAT2)
EMMC_MSC0_D3: R73.2 R137.2 U11.B2(DAT3)
EMMC_RST_PB21: C92.1 R79.1 U11.K5(RSTN) ; also on sheet 5
EMMC_VDDI: C93.1 U11.C2(VDDI)
EXCLKI: C66.2 R41.2 U7.C1(EXCLK_XIN) Y1.1
EXCLKO: C67.2 R41.1 U7.D2(EXCLK_XOUT) Y1.3
HPOUT: C76.2 U7.T1(HPOUTL)
I2C0_MIPI_DVP_SCK: J10.3 J11.20 TP29.1 ; also on sheet 5
I2C0_MIPI_DVP_SDA: J10.6 J11.19 TP28.1 ; also on sheet 5
I2C1_SCK_PB26: R152.1 U21.6(SCL) ; also on sheet 5
I2C1_SDA_PB25: R140.1 U21.5(SDA) ; also on sheet 5
IRLED_EN_N_PB19: C102.2 Q8.1(GATE) R165.1 ; also on sheet 5
KEY1_PB30: R89.1 SW1.2 ; also on sheet 5
KEY_IoT_N: C95.2 D10.2(CATHODE) R90.2 SW2.1 ; also on sheet 3
LDR0: R216.2 ; also on sheet 6
LED_G: R94.1 ; also on sheet 5
LED_R_IoT: R95.1 ; also on sheet 3
MCU_PWR: R54.1 R90.1 R93.1 ; also on sheet 3 5 9
MICBIAS: C141.1 C142.1 R83.2 U7.P3(MICBIAS)
MICNL: C65.2 C78.1 D15.2(CATHODE) J7.1 R69.1
MICPL: C64.2 C78.2 D9.2(CATHODE) J7.2 R80.2
MIPI1_2LANE_3V3: J11.30 R129.2
MIPI1_2LANE_5V: J11.28 J11.29 R128.2
MIPI_DVP_IRCUTN_PB18: J10.31 J11.25 ; also on sheet 5
MIPI_DVP_IRCUTP_PB17: J10.32 J11.24 ; also on sheet 5
MIPI_DVP_MCLK: R125.1 R126.1 TP27.1 ; also on sheet 5
MIPI_DVP_PWDN_PA19: J10.25 J11.26 TP31.1 ; also on sheet 5
MIPI_DVP_RESET: J10.33 J11.18 TP30.1 ; also on sheet 5
MIPI_MCLK_PA15: J11.22 R125.2 TP32.1
MIPI_RX_2LANE_CLKN0: J11.2 R110.2
MIPI_RX_2LANE_CLKP0: J11.3 R108.2
MIPI_RX_2LANE_DN0: J11.5 R102.2
MIPI_RX_2LANE_DN1: J11.8 R106.2
MIPI_RX_2LANE_DP0: J11.6 R100.2
MIPI_RX_2LANE_DP1: J11.9 R104.2
MSC0_CLK: R85.1 R86.1 ; also on sheet 5
MSC0_CMD: R82.1 R84.1 ; also on sheet 5
MSC0_D0: R87.1 R131.1 ; also on sheet 5
MSC0_D1: R132.1 R133.1 ; also on sheet 5
MSC0_D2: R134.1 R135.1 ; also on sheet 5
MSC0_D3: R136.1 R137.1 ; also on sheet 5
OSC32_XI: C71.2 R52.2 U7.M16(OSC32_XI) Y3.2
OSC32_XO: C72.2 R52.1 U7.M15(OSC32_XO) Y3.1
OU_PWR_EN_PC18: D12.2 R233.1 ; also on sheet 4
PLL_AVDD18: C59.1 C60.1 FB3.1 U7.D3(PLL_AVDD)
POR_CTRL: R121.2 R122.2 U7.K16(POR_CTL)
PWRON: TP12.1 U7.K15(PWRON)
RST_OUT: TP14.1 U7.J16(RST_OUT)
RTC_0V8: C99.1 C143.1 TP34.1 U7.L15(VDD_RTC) U13.5(VOUT)
RTC_1V8: C94.1 C98.1 C169.1 R97.2 R121.1 R142.1 TP36.1 U7.L17(VDDIO_RTC) U12.5(VOUT) U13.1(VIN)
RTC_IRQ_N_PB29: R153.1 U21.3(INT) ; also on sheet 5
SD0_CD_N_PB27: J6.9(CD) R88.1 ; also on sheet 5
SD0_MSC0_CLK: J6.5(CLK) R85.2
SD0_MSC0_CMD: J6.3(CMD) R61.2 R82.2
SD0_MSC0_D0: J6.7(DAT0) R62.2 R87.2
SD0_MSC0_D1: J6.8(DAT1) R63.2 R132.2
SD0_MSC0_D2: J6.1(DAT2) R64.2 R134.2
SD0_MSC0_D3: J6.2(DAT3) R65.2 R136.2
SD_PWR_EN_N_PB20: C82.2 Q3.1(GATE) R66.2 ; also on sheet 5
SFC_CS_N: R44.1 U7.T4(SFC0_CE_PA28) U8.1(~{CS})
SFC_SCLK: R43.1 U8.6(SCLK)
SFC_SIO0: U7.U5(SFC0_DT_IO0_PA23) U8.5(SI/SIO0)
SFC_SIO1: U7.R5(SFC0_DR_IO1_PA24) U8.2(SO/SIO1)
SFC_SIO2: U7.T5(SFC0_WP_IO2_PA26) U8.3(~{WP}/SIO2)
SFC_SIO3: U7.T6(SFC0_HOLD_IO3_PA25) U8.7(~{RESET}/SIO3)
SOC_0V8: C46.1 C47.1 C48.1 C49.1 C50.1 C51.1 C52.1 C53.1 C54.1 C55.1 C56.1 C57.1 FB4.1 R31.1 U7.H5(VDD1) U7.H6(VDD2) U7.H7(VDD3) U7.H8(VDD4) U7.H9(VDD5) U7.H10(VDD6) U7.H11(VDD7) U7.H12(VDD8) U7.H13(VDD9) U7.J5(VDD10) U7.J13(VDD11) U7.K5(VDD12) U7.K13(VDD13) U7.L5(VDD14) U7.M5(VDD15) U7.M6(VDD16) U7.N6(VDD17) U7.N7(VDD18) U7.N8(VDD19) U7.N9(VDD20) U7.N10(VDD21) ; also on sheet 5
SOC_1V8: C63.1 C176.1 C177.1 FB2.2 FB3.2 FB5.1 FB7.1 FB8.1 R20.1 U7.N11(VDDIO18_1) ; also on sheet 4 5
SOC_3V3: FB6.1 R19.1 ; also on sheet 4 5
SOC_PWR_EN_IoT: D12.1 ; also on sheet 3
SPEAK_EN: R58.1 U10.1(/SD) ; also on sheet 5
TEST_TE: TP16.1 U7.L13(TEST_TE)
TRST_: TP15.1 U7.D14(TRST_)
USB_AVD08: C135.1 C136.1 FB4.2 U7.R4(USB_AVD08)
USB_AVD18: C137.1 C138.1 FB5.2 U7.T3(USB_AVD18)
USB_AVD33: C139.1 C140.1 FB6.2 U7.R3(USB_AVD33)
USB_DM0: U7.U1(USB0PN) ; also on sheet 9
USB_DP0: U7.T2(USB0PP) ; also on sheet 9
USB_ID: R55.1 U7.U2(USB0ID)
USB_VBUS: R24.1 R27.1 U7.U3(VBUS)
VCM: C68.1 C69.1 U7.R2(VCM)
WIFI_VBAT: R13.1 TP4.1 ; also on sheet 3
WKUP: TP13.1 U7.J17(WKUP_PD31)
N6875993: D7.2(CATHODE) J5.1 U10.8(VO-)
N6876005: D6.2(CATHODE) J5.2 U10.5(VO+)
N6876073: C77.1 R56.1 R57.1 U10.6(VDD)
N6876131: R60.1 U10.4(-IN)
N6876183: C76.1 R60.2
N6876193: C75.1 R59.2
N7727802: D11.3 R95.2
N7727853: D11.2 R94.2
N16597671: R59.1 U10.3(+IN)
N16626294: R15.1 U2.4(EN)
N16626314: C10.1 C11.1 R14.2 R15.2 U2.5(VIN)
N16626426: R16.1 R17.2 U2.3(FB)
N16626534: C28.1 C29.1 C34.1 L5.2 R30.2 R33.2 TP8.1 U5.6(OUT)
N16626558: C34.2 R33.1 R36.2 U5.1(FB)
N16626586: C24.2 R25.1 R28.2 U3.1(FB)
N16626718: L5.1 U5.4(SW)
N16626738: L3.1 U3.4(SW)
N16627048: C206.1 R32.2 U5.5(EN)
N16627266: L2.1 U2.1(SW)
N16627350: C96.1 R22.2 U3.5(EN)
N16676856: C25.2 R23.1 R29.2 U4.1(FB)
N16676932: L4.1 U4.4(SW)
N16677062: C205.1 R26.2 U4.5(EN)
N16732442: R43.2 U7.R6(SFC0_CLK_PA27)
N16973565: R116.2 U7.F13(DDR_ZQ)
N16973568: R117.2 U7.D9(RZQ)
N16981740: C64.1 U7.N3(MICPL)
N16981743: C65.1 U7.P2(MICNL)
N16981952: R120.2 U7.D4(EFUSE_AVDD)
N16990829: C85.1 R81.1 R83.1
N16990879: C79.2 R80.1 R81.2
N16990962: C79.1 R67.1 R69.2
N16994187: R142.2 U13.3(EN)
N16994244: C100.1 U13.4(BP/FB)
N16994305: C97.1 U12.4(BP/FB)
N16994361: R141.2 U12.3(EN)
N17141430: C15.2 J3.1 Q1.1(GATE) Q2.3(COLLECTOR) R21.2
N17141450: D12.3 R231.2
N17141452: C15.1 Q1.2(SOURCE) R18.2 R21.1
N17141508: Q2.1(BASE) R231.1 R232.2
N17141576: D13.1(ANODE) R234.2
N17211450: C158.2 U21.1(OSCI) Y2.2
N17211478: C159.2 U21.2(OSC0) Y2.1
N17219479: C107.1 D14.1(ANODE) Q8.3(DRAIN) R167.1
N17219520: D14.2(CATHODE) D16.1(ANODE)
N17219530: D16.2(CATHODE) R159.1
N17242896: C32.1 C33.1 C35.1 L6.2 R31.2 R35.2 TP9.1 U14.6(OUT)
N17242898: C35.2 R35.1 R37.2 U14.1(FB)
N17242946: L6.1 U14.4(SW)
N17243021: C108.1 R34.2 U14.5(EN)
N17251040: R208.1 U6.4(EN)
N17251042: C164.1 C165.1 R173.2 R208.2 U6.5(VIN)
N17251086: R91.1 R96.1 U6.3(FB)
N17251195: L8.1 U6.1(SW)
N17299915: R216.1 U7.P15(SADC_VIN0)

Not connected (* = marked no-connect by the designer): D11 1(ANODE)*; J10 4* 5* 23* 24* 30*; J11 11* 12* 14* 15* 17*; U2 2(NC)*; U6 2(NC)*; U7 L16(PPRST_)*; U10 2(NC); U21 7(CLKOUT)*

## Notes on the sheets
sheet 10
- POWER-SUPPLY
- NC
- 1.8V/600mA MAX
- 3.3V/600mA MAX
- 1.11V
- NC
- 1.11V
- NC
- VOUT=(1+620k/1M)*1.11=1.798V
- VOUT=(1+1M/499K)*1.11=3.334V
- 测试功耗时需要NC 掉
- 3.3V/1A MAX
- 1.8V/1A MAX
- 0.6V
- 0.6V
- NC
- NC
- VOUT=(1+1M/221K)*0.6=3.315V
- VOUT=(1+1M/499K)*0.6=1.802V
- 0.8V/2A MAX
- 1.5V/1A MAX
- 0.6V
- 0.6V
- VOUT=(1+750K/499KK)*0.6=1.502V
- VOUT=(1+249K/750K)*0.6=0.799V
- VCC_DDR=(1+499K/250K)*0.6=1.8V for DDR2
- VCC_DDR=(1+750K/499K)*0.6=1.5V for DDR2L or DDR3
- √
- VCC_DDR=(1+750K/600K)*0.6=1.35V for DDR3L
- INGENIC SEMICONDUCTOR CO.,LTD
- Note：The jumper in         is used for measuring power consumption
  and can be removed in the product board.
sheet 11
- T41-POWER
- INGENIC SEMICONDUCTOR CO.,LTD
sheet 12
- T41_SYS_APeripheral
- CLK
- NC
- POR CTRL
- NOR FLASH
- 1    POR
- NC
- 0    PPRST
- RTC_CLK
- NC
- Decap
- Close to Micbias Pin(P3)
- INGENIC SEMICONDUCTOR CO.,LTD
sheet 13
- SD_AUDIO_EMMC
- NC
- SD CARD
- SPK
- MICL
- -
- NC
- +
- NC
- NC
- Reserved
- EMMC
- NC
- NC
- NC
- NC
- NC
- NC
- NC
- INGENIC SEMICONDUCTOR CO.,LTD
sheet 14
- KEY_LED_RTC_BOOT
- KEY
- INT  RTC
- 1.8V/250mA
- 0.8V/300mA
- NC
- LED
- BOOT
- NC
- EXT  RTC
- BOOT_SEL1
- BOOT_SEL0
- BOOT FROM
- 0
- 0
- MMC/SD boot@MSC0(MMC/SD use GPIO Port B.
  MSC1 use GPIO Port C)
- 1
- 0
- UART boot @ CS2(Ymodem@115200/9600)
- 1
- 1
- 0
- 1
- SFC boot @ CS4(SPI boot)
- USB boot @USB2.0 device, EXTCLK=24MHz
- INGENIC SEMICONDUCTOR CO.,LTD
sheet 15
- DVP
- MIPI_DVP_CAMERA
- NC
- NC
- NC
- NC
- NC
- NC
- NC
- Note：The 0Ω resistance in             is used for measuring power consumption
  and can be removed in the product board.
- MIPI 2Lane CAMERA 1
- IRLED
- INGENIC SEMICONDUCTOR CO.,LTD
sheet 16
- Date
- Revision
- Change
- Sep 20 2022
- Rev1.0
- 1. First Revision
- Nov 01 2022
- Rev1.1
- 1.T41.G3&F2 Ball  Change to NC.
- 2.ADC Channel Series 4.7R Resistor.
- 3.Update T41 package
- INGENIC SEMICONDUCTOR CO.,LTD
